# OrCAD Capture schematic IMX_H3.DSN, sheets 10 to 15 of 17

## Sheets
10 PAGE11 - ISM: size C
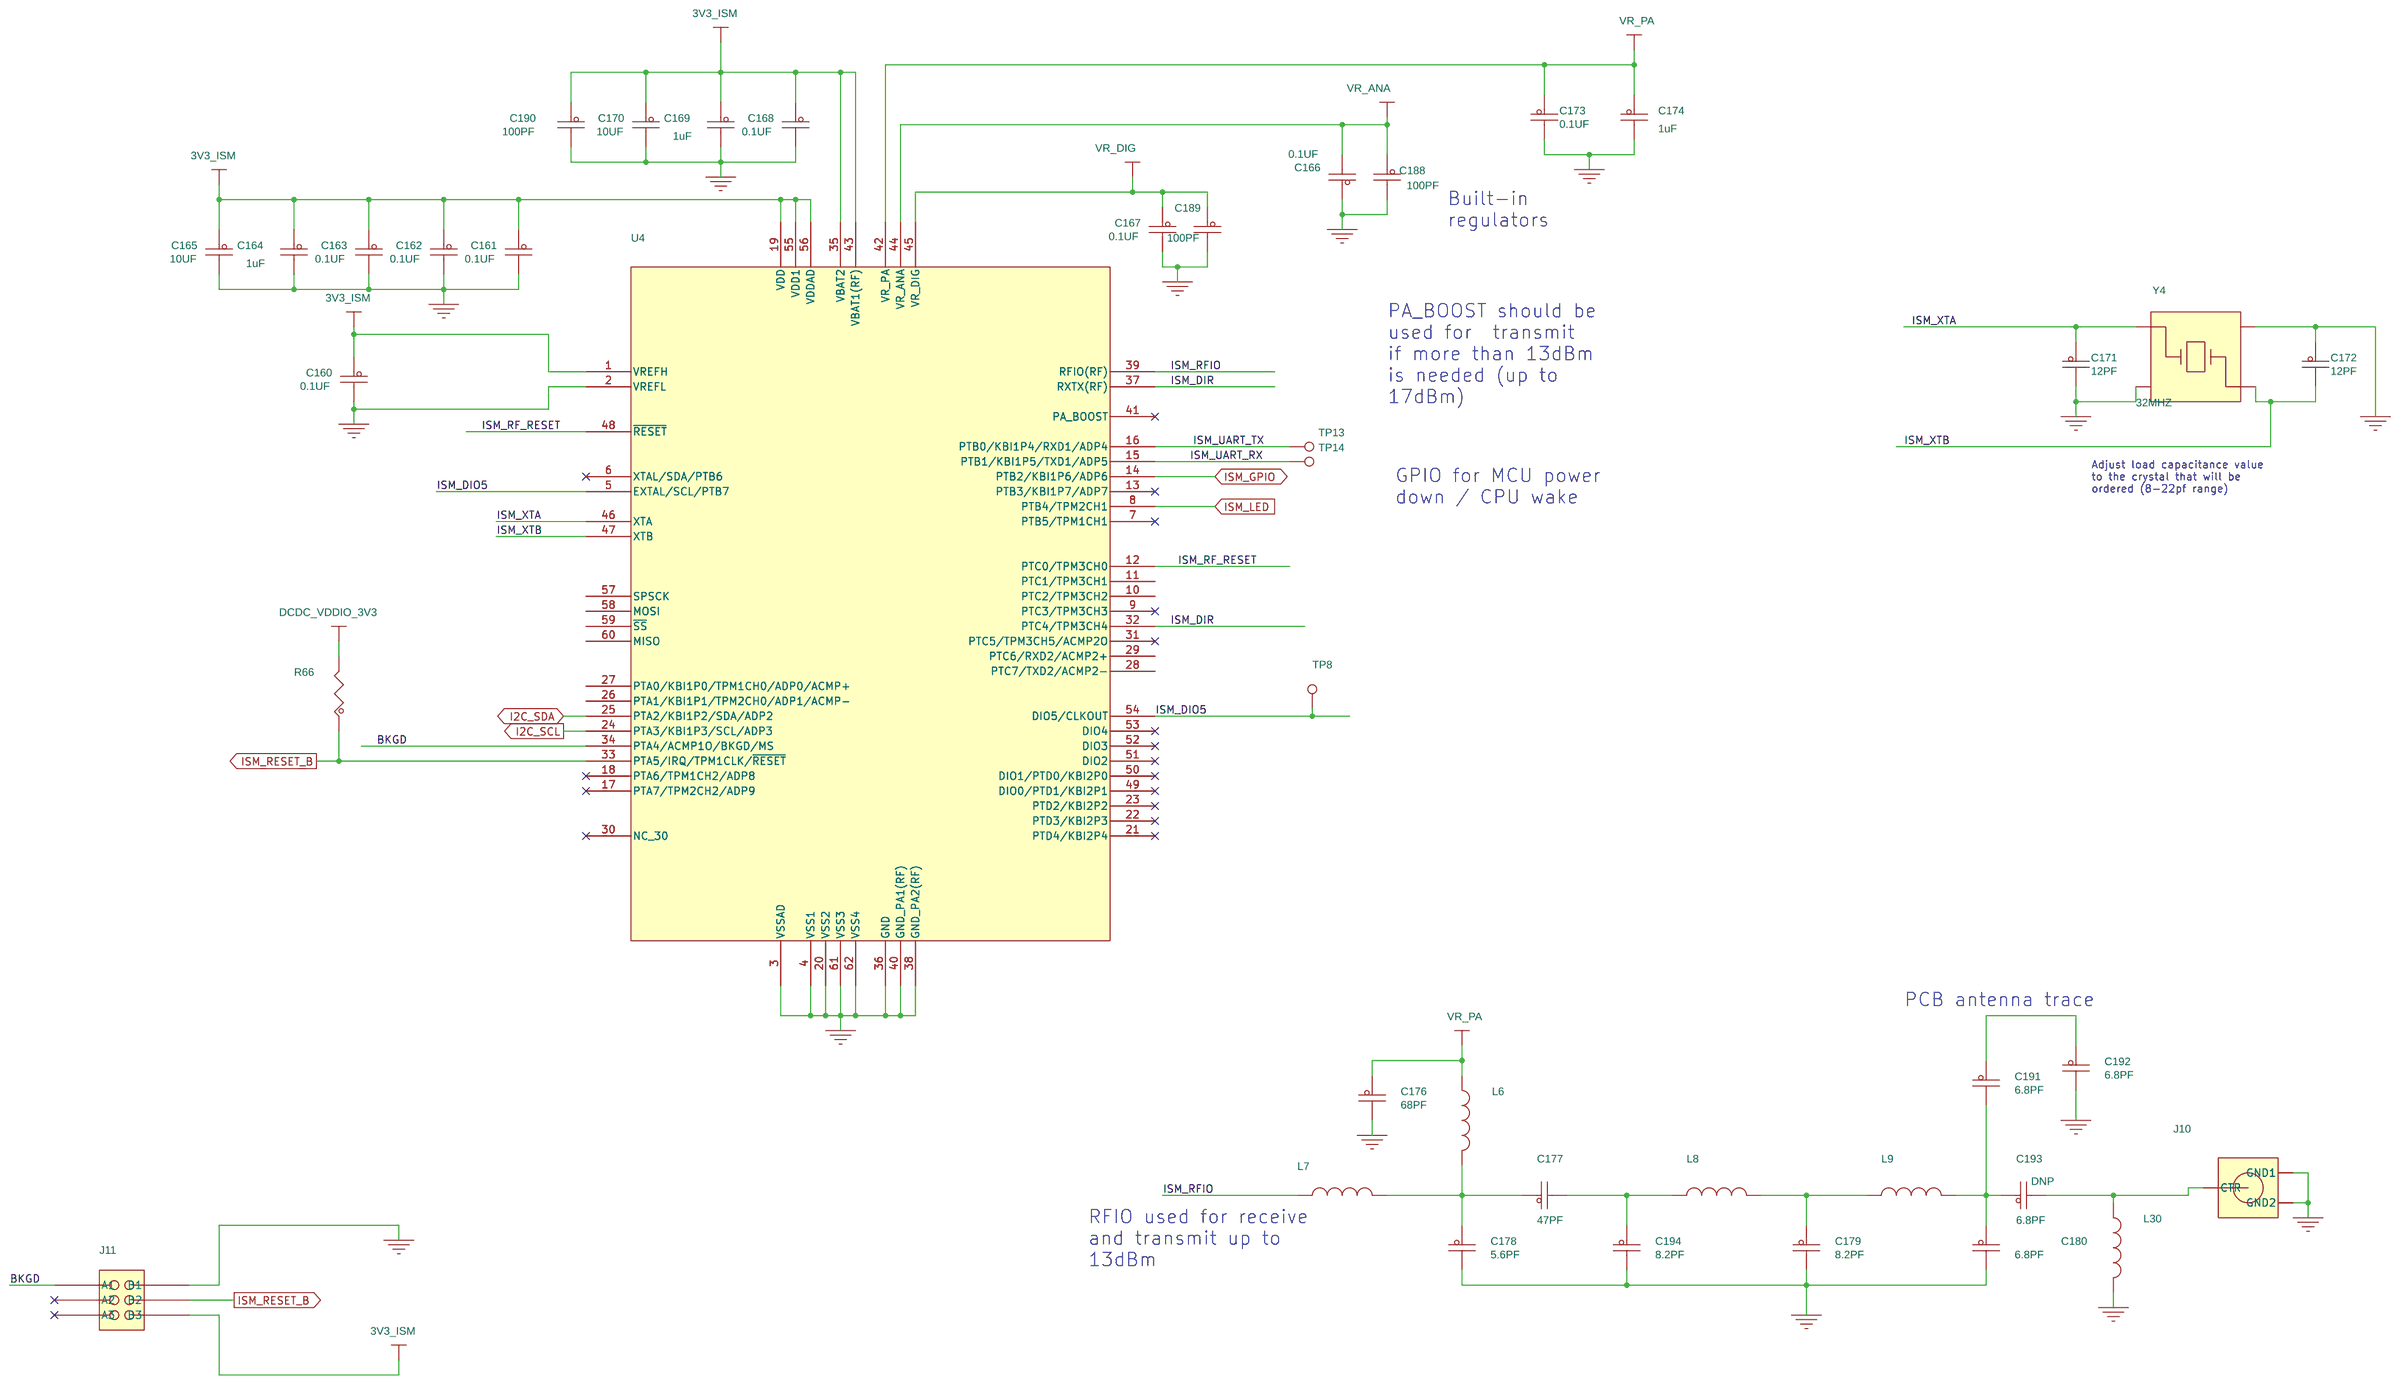
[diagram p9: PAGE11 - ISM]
11 PAGE12 - Zigbee: size C
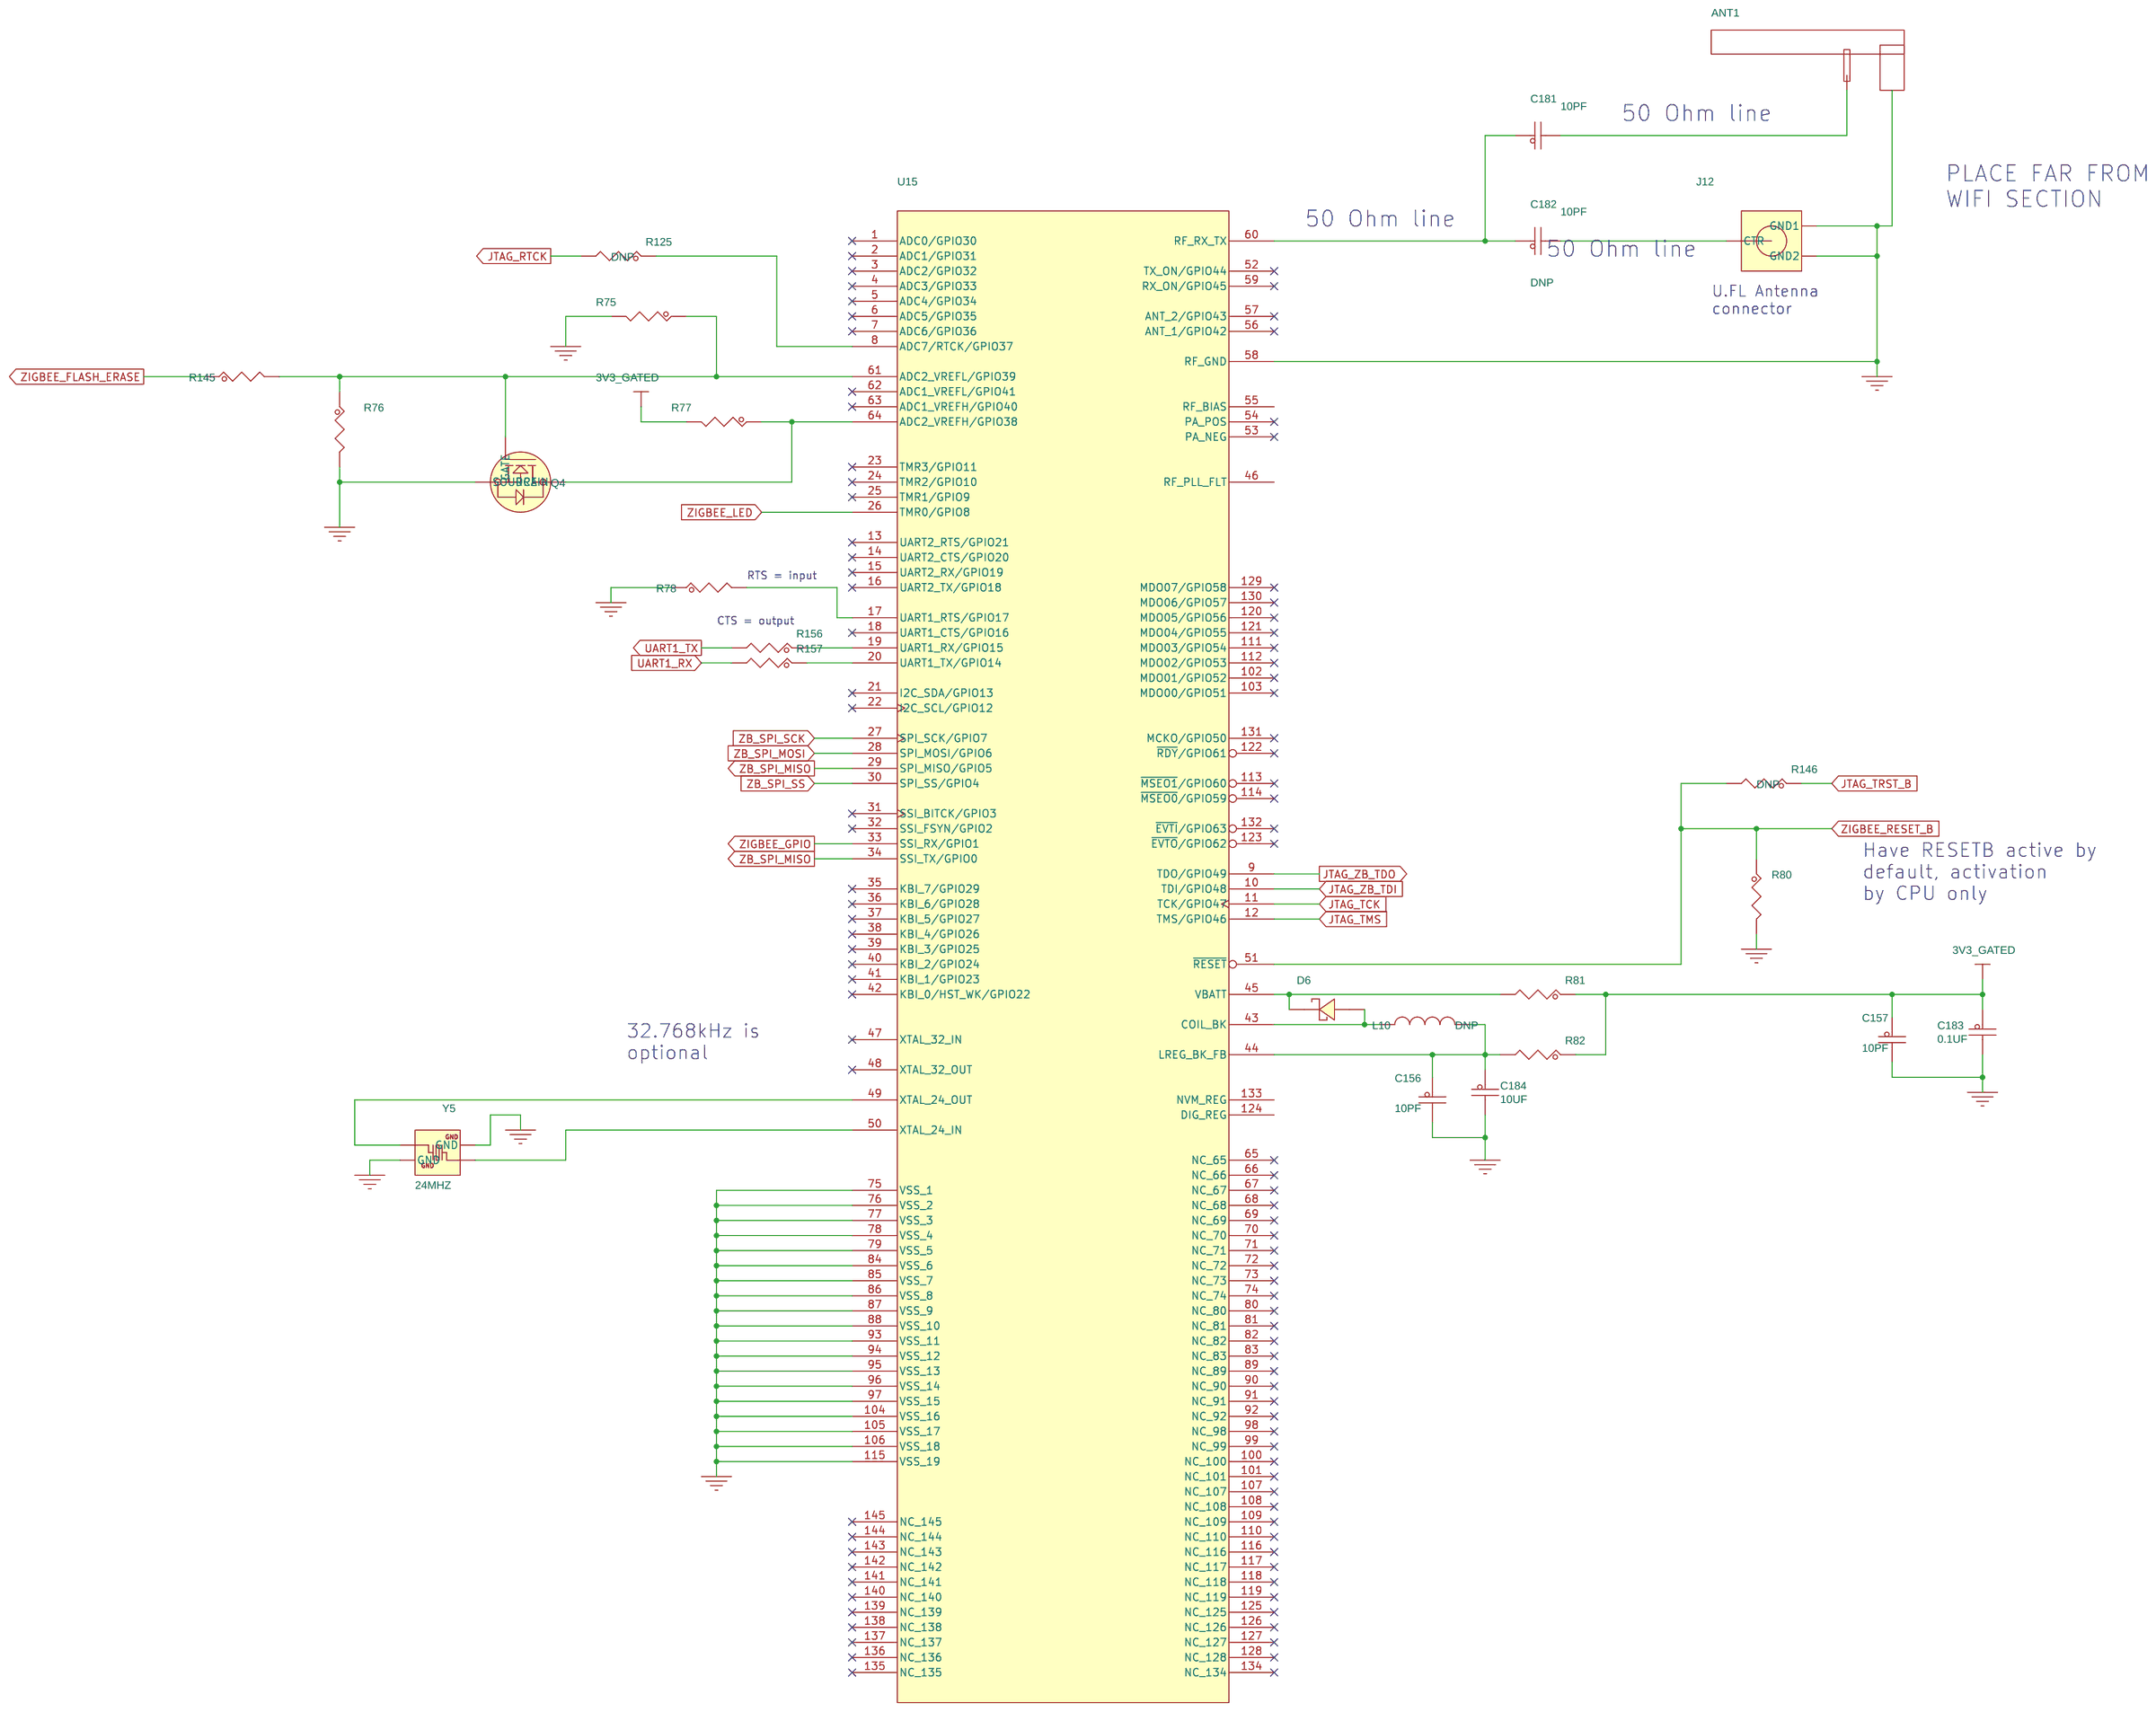
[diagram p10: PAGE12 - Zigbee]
12 PAGE13 - Audio: size C
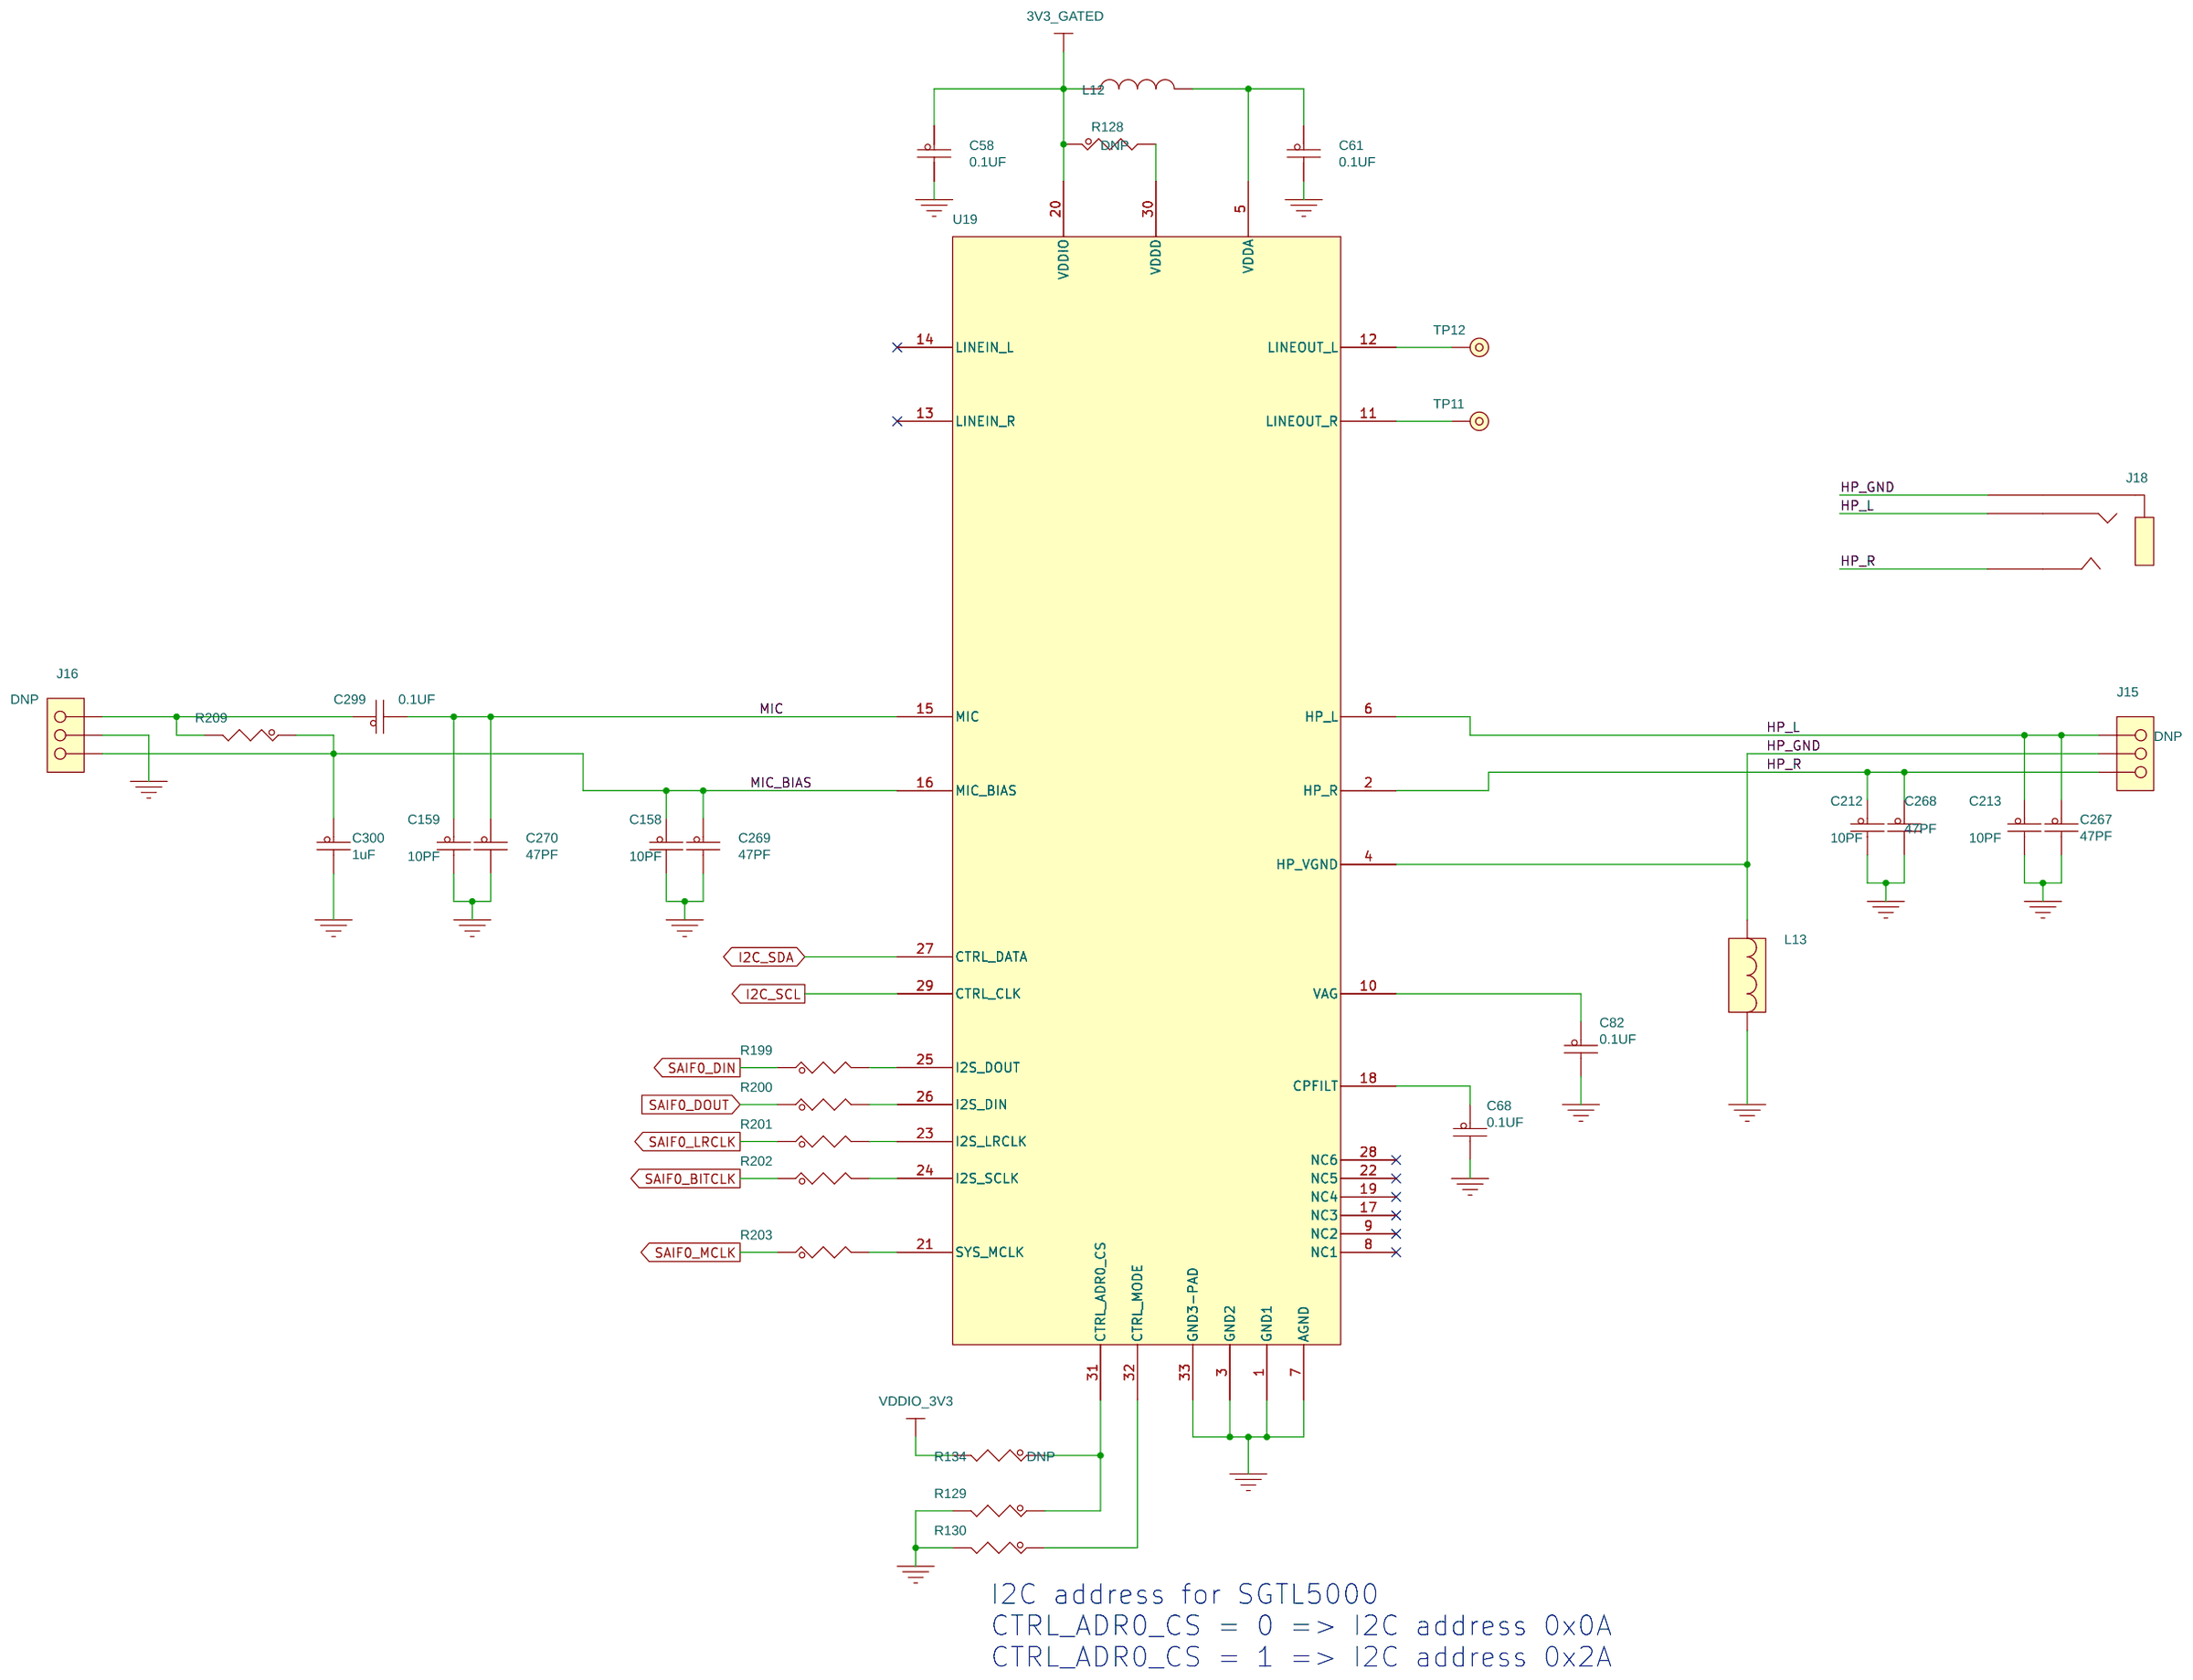
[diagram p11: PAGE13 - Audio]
13 PAGE14 - BlueTooth-WIFI: size C
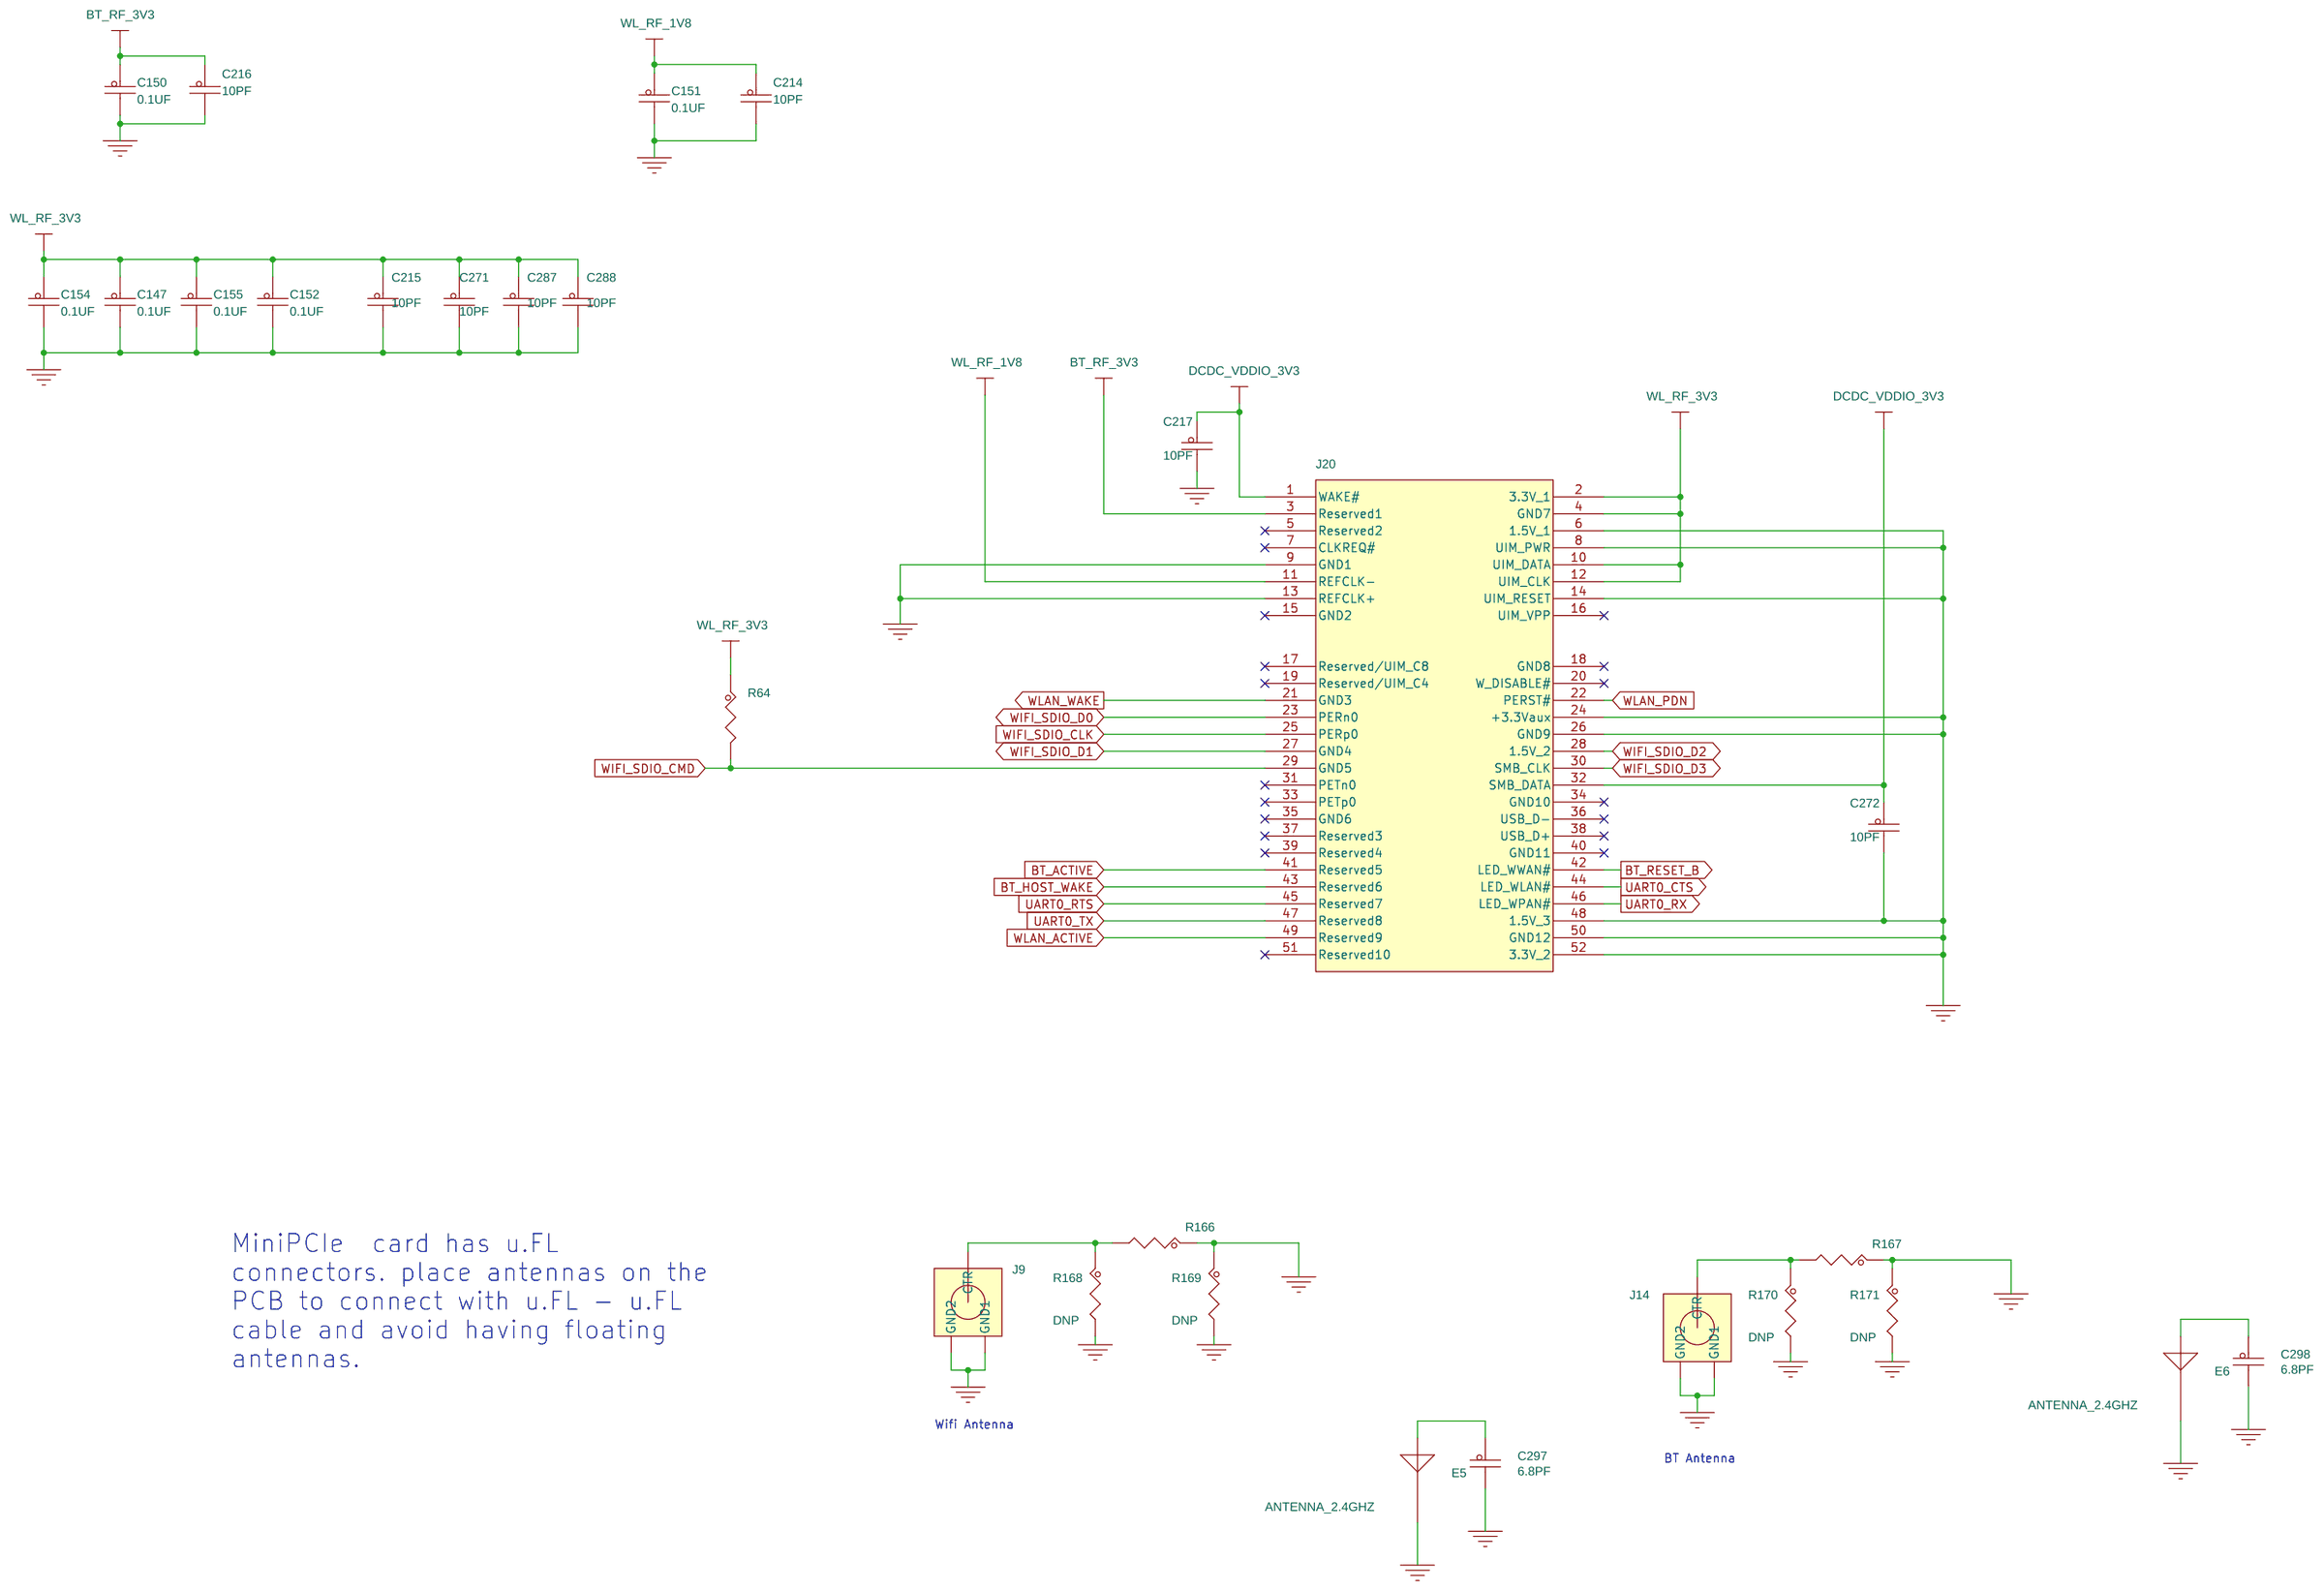
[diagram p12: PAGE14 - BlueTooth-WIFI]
14 PAGE15 - USB HUB: size C
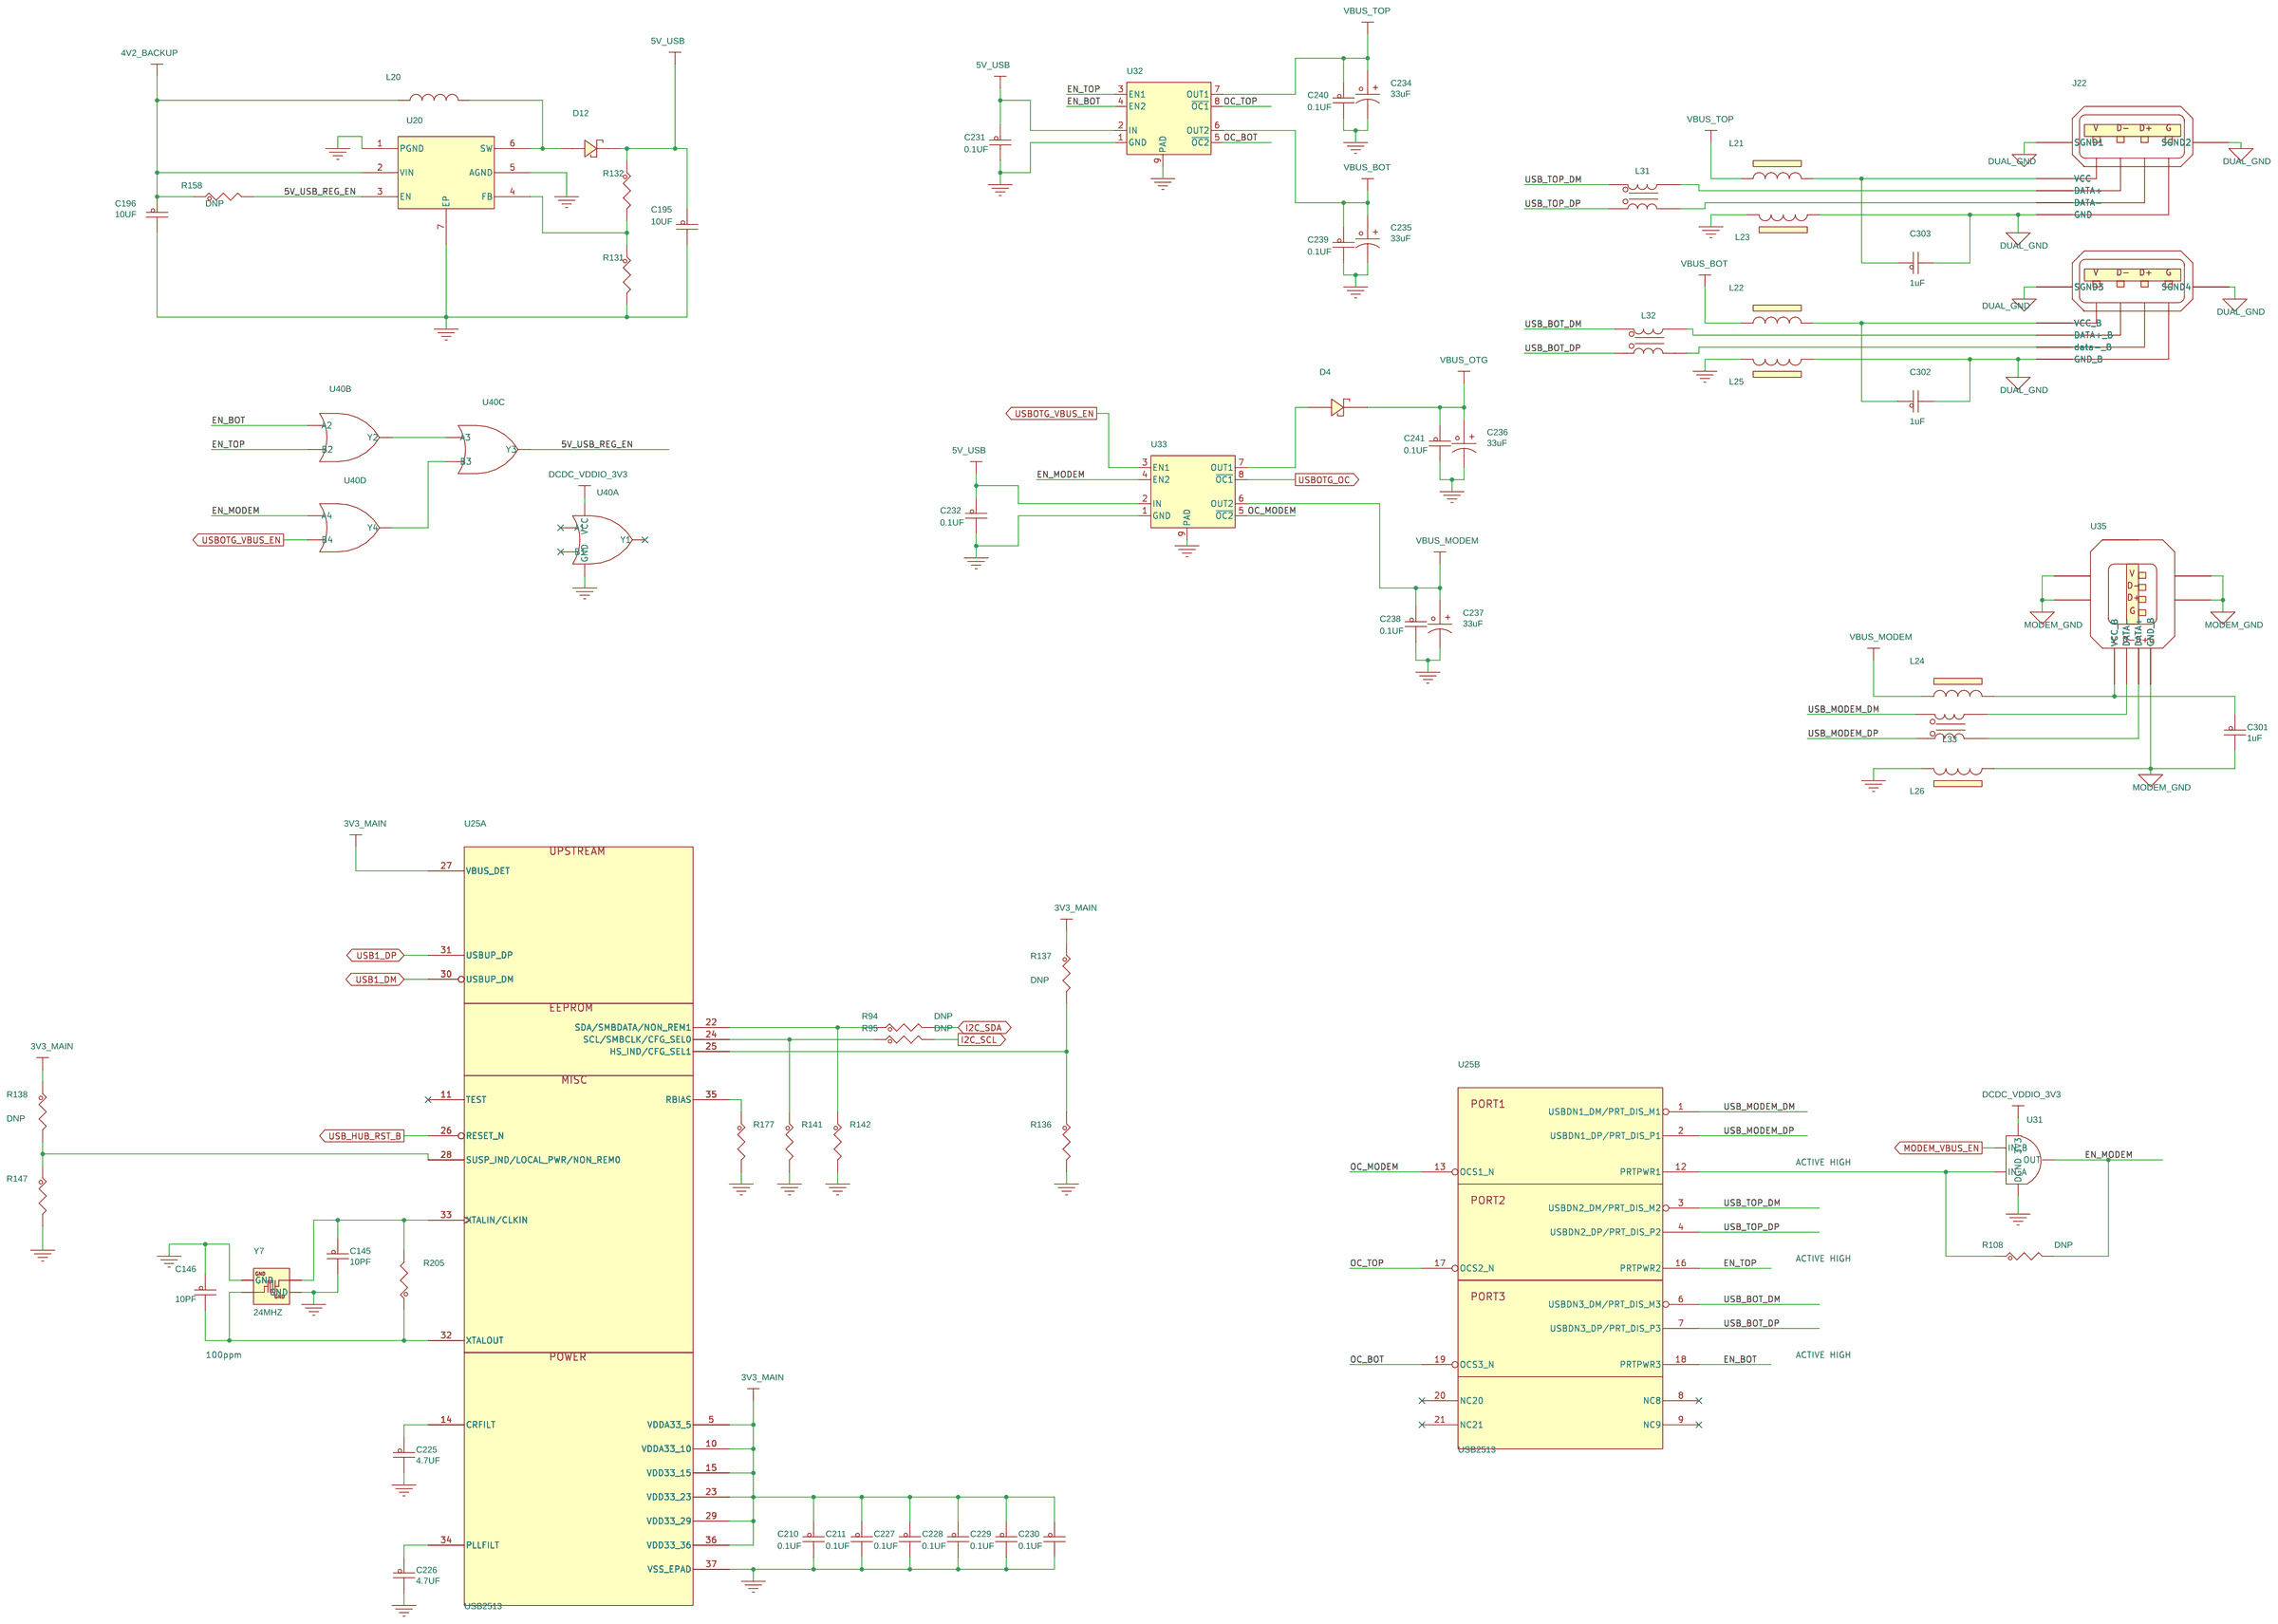
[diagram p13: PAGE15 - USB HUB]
15 PAGE16 - NFC , IO expander: size C
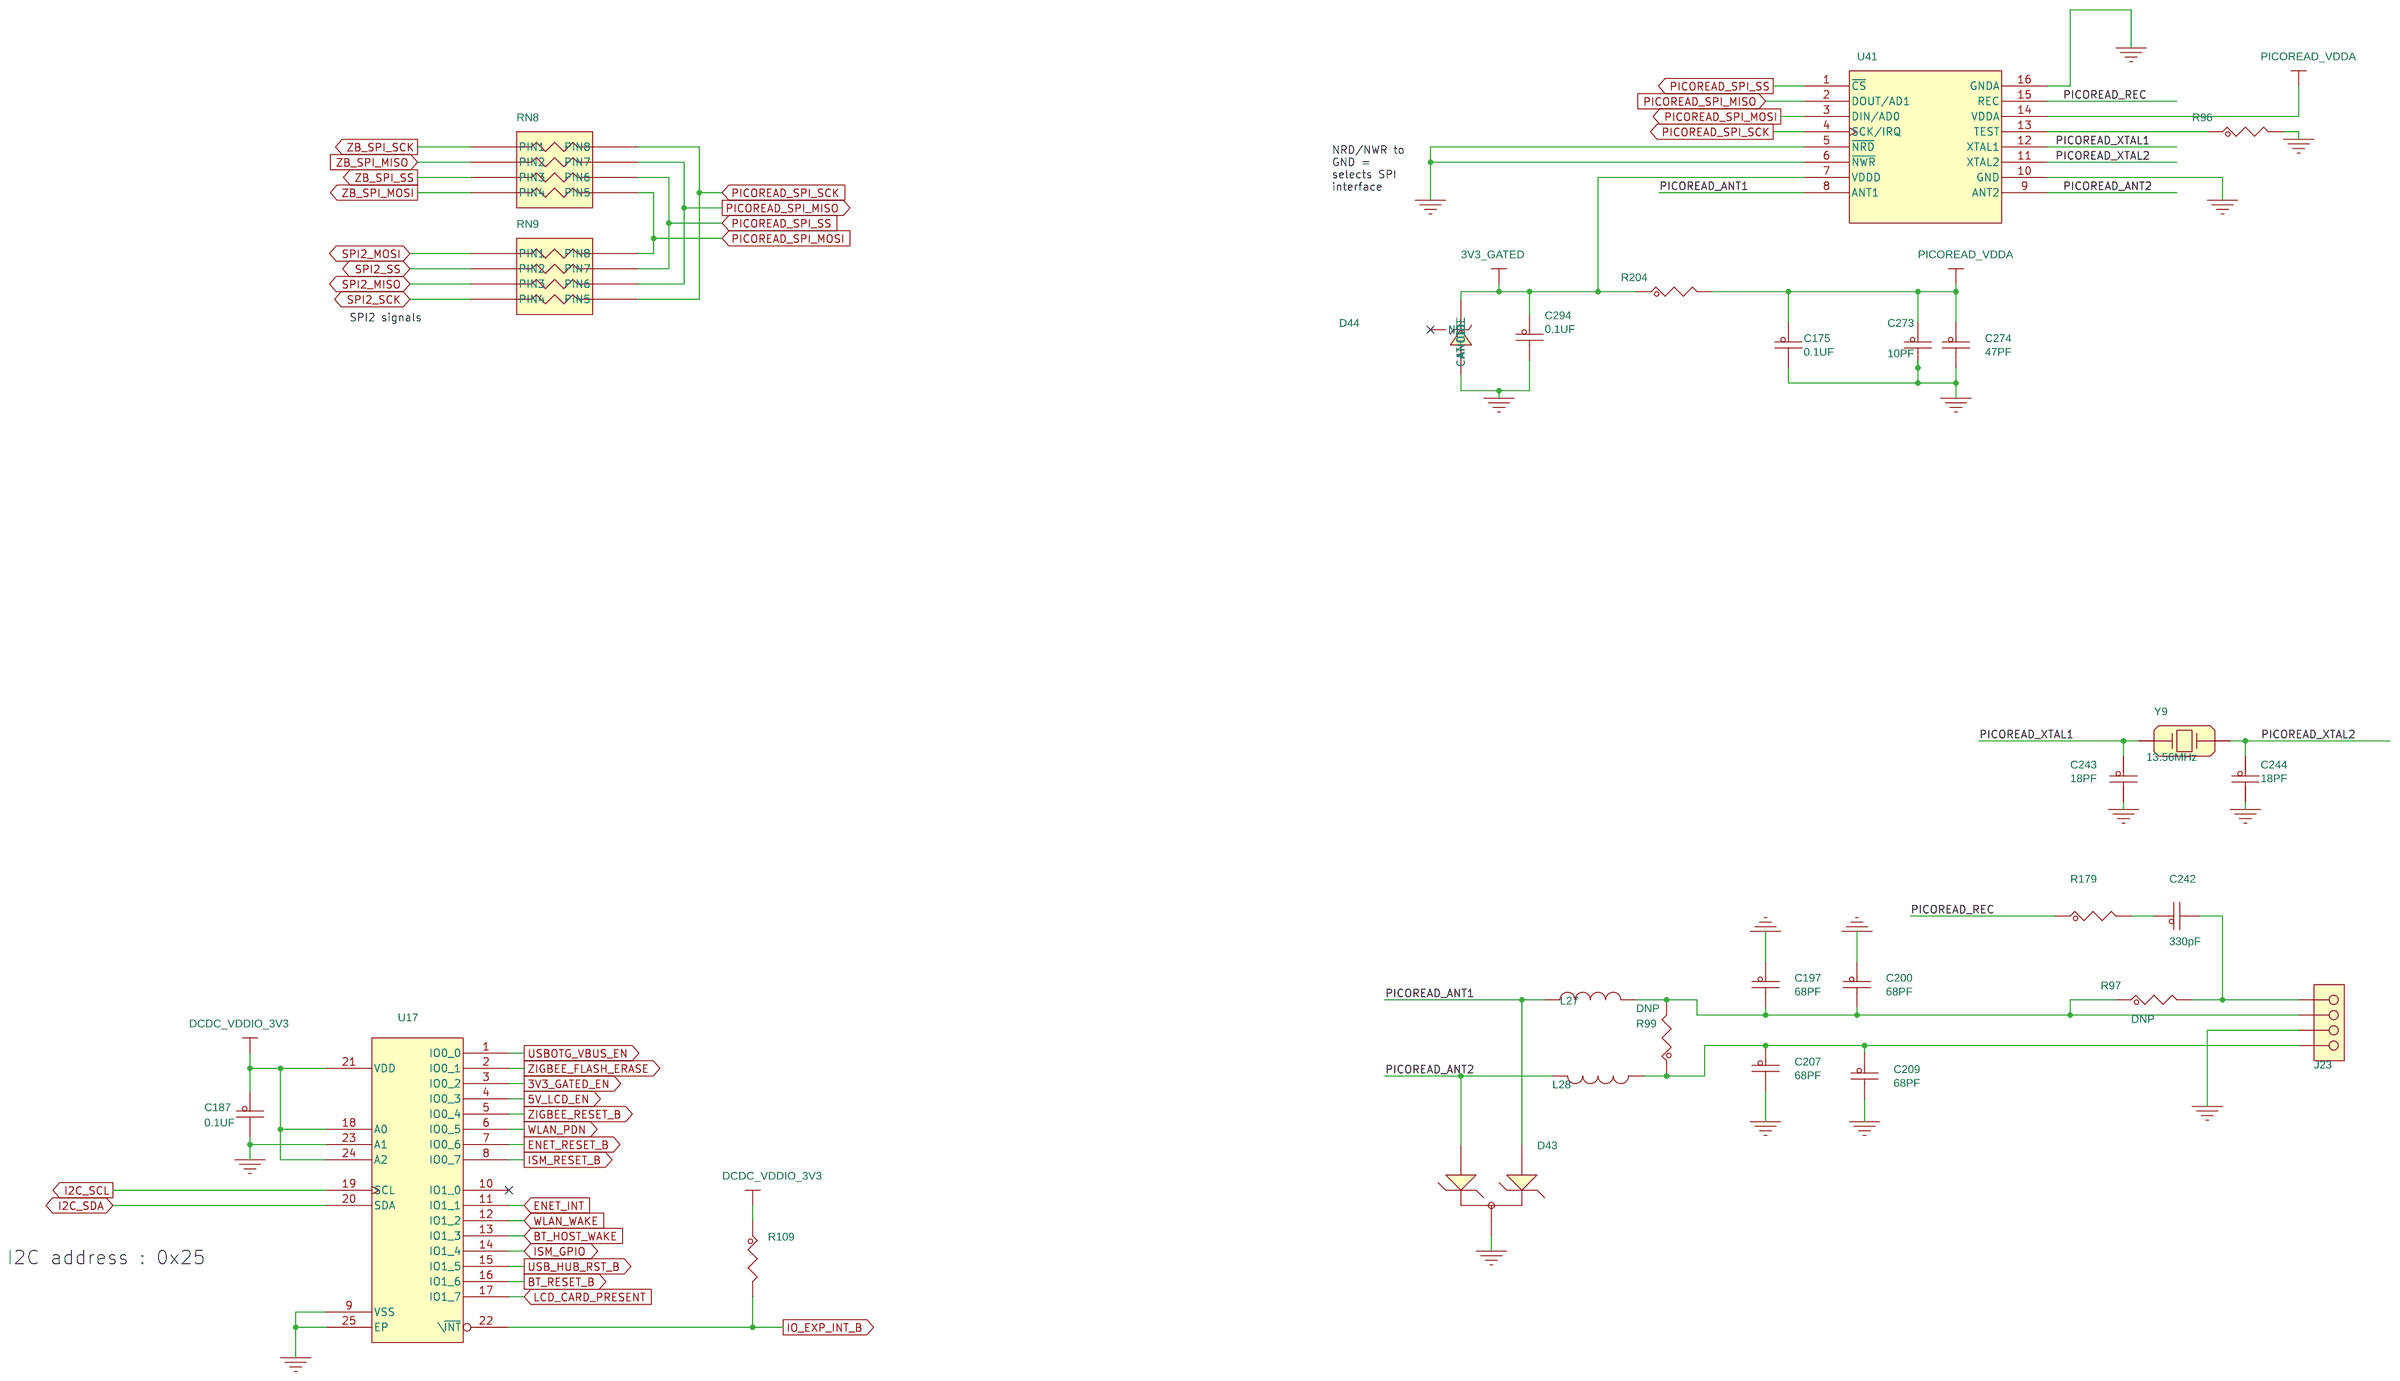
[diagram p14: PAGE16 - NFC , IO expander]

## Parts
sheet PAGE11 - ISM
C160  0.1UF  [CC0402_25]
C161  0.1UF  [CC0402_25]
C162  0.1UF  [CC0402_25]
C163  0.1UF  [CC0402_25]
C164  1uF  [CC0603_OV]
C165  10UF  [CC0805_OV]
C166  0.1UF  [CC0402_25]
C167  0.1UF  [CC0402_25]
C168  0.1UF  [CC0402_25]
C169  1uF  [CC0603_OV]
C170  10UF  [CC0805_OV]
C171  12PF  [CC0402_25]
C172  12PF  [CC0402_25]
C173  0.1UF  [CC0402_25]
C174  1uF  [CC0603_OV]
C176  68PF  [CC0402_25]
C177  47PF  [CC0402_25]
C178  5.6PF  [CC0402_25]
C179  8.2PF  [CC0402_25]
C180  6.8PF  [CC0402_25]
C188  100PF  [CC0402_25]
C189  100PF  [CC0402_25]
C190  100PF  [CC0402_25]
C191  6.8PF  [CC0402_25]
C192  6.8PF  [CC0402_25]
C193  6.8PF  [CC0402_25]
C194  8.2PF  [CC0402_25]
J10  U.FL  [CON_3_UFL_R_SMT]
J11  HDR_2X3  [HDR203_TSM2_SM]
L6  33nH  [IND_0402]
L7  4.7NH  [IND_0402]
L8  6.8NH  [IND_0402]
L9  6.8NH  [IND_0402]
L30  LQW18ANR27G00  [IND_0603A]
R66  10.0K  [RC0402_25]
TP8  35 MIL  [TESTPOINT_35MIL]
TP13  35 MIL  [TESTPOINT_35MIL]
TP14  35 MIL  [TESTPOINT_35MIL]
U4  MC12311  [lga60_0p5_8x8]
Y4  32MHZ  [xtlosc4_3p2x2p5mm_sm]
sheet PAGE12 - Zigbee
ANT1  F_Antenna  [f_antenna_dig528-2]
C156  10PF  [CC0402_25]
C157  10PF  [CC0402_25]
C181  10PF  [CC0402_25]
C182  10PF  [CC0402_25]
C183  0.1UF  [CC0402_25]
C184  10UF  [CC0805_OV]
D6  MBR0520LT1G  [SOD123]
J12  U.FL  [CON_3_UFL_R_SMT]
L10  100UH  [IND_VLF4018]
Q4  NTS4001NT1G  [sc70_3]
R75  10.0K  [RC0402_25]
R76  10.0K  [RC0402_25]
R77  10.0K  [RC0402_25]
R78  0  [RC0402_25]
R80  10.0K  [RC0402_25]
R81  0  [RC0402_25]
R82  0  [RC0402_25]
R125  0  [RC0402_25]
R145  0  [RC0402_25]
R146  0  [RC0402_25]
R156  0  [RC0402_25]
R157  0  [RC0402_25]
U15  MC13226V  [lga145_9p5_sq]
Y5  24MHZ  [xtlosc4_3p2x2p5mm_sm]
sheet PAGE13 - Audio
C58  0.1UF  [CC0402_25]
C61  0.1UF  [CC0402_25]
C68  0.1UF  [CC0402_25]
C82  0.1UF  [CC0402_25]
C158  10PF  [CC0402_25]
C159  10PF  [CC0402_25]
C212  10PF  [CC0402_25]
C213  10PF  [CC0402_25]
C267  47PF  [CC0402_25]
C268  47PF  [CC0402_25]
C269  47PF  [CC0402_25]
C270  47PF  [CC0402_25]
C299  0.1UF  [CC0402_25]
C300  1uF  [CC0603_OV]
J15  HDR_1X3  [hdr103_78mil]
J16  HDR_1X3  [hdr103_78mil]
J18  AUD 3  [con_aud_3_th_ra]
L12  470OHM  [IND_0603]
L13  75 OHM  [IND_0402]
R128  0  [RC0402_25]
R129  0  [RC0402_25]
R130  0  [RC0402_25]
R134  10.0K  [RC0402_25]
R199  10  [RC0402_25]
R200  10  [RC0402_25]
R201  10  [RC0402_25]
R202  10  [RC0402_25]
R203  10  [RC0402_25]
R209  0  [RC0402_25]
TP11  TEST_POINT  [testpoint_060_035mil]
TP12  TEST_POINT  [testpoint_060_035mil]
U19  SGTL5000 32QFN  [qfn32]
sheet PAGE14 - BlueTooth-WIFI
C147  0.1UF  [CC0402_25]
C150  0.1UF  [CC0402_25]
C151  0.1UF  [CC0402_25]
C152  0.1UF  [CC0402_25]
C154  0.1UF  [CC0402_25]
C155  0.1UF  [CC0402_25]
C214  10PF  [CC0402_25]
C215  10PF  [CC0402_25]
C216  10PF  [CC0402_25]
C217  10PF  [CC0402_25]
C271  10PF  [CC0402_25]
C272  10PF  [CC0402_25]
C287  10PF  [CC0402_25]
C288  10PF  [CC0402_25]
C297  6.8PF  [CC0402_25]
C298  6.8PF  [CC0402_25]
E5  ANTENNA_2.4GHZ  [antenna_3316]
E6  ANTENNA_2.4GHZ  [antenna_3316]
J9  U.FL  [CON_3_UFL_R_SMT]
J14  U.FL  [CON_3_UFL_R_SMT]
J20  CON 2X26 MINI PCI EXPRESS  [con_2x26_0p8_smt_a]
R64  22K  [RC0402_25]
R166  0  [RC0402_25]
R167  0  [RC0402_25]
R168  0  [RC0402_25]
R169  0  [RC0402_25]
R170  0  [RC0402_25]
R171  0  [RC0402_25]
sheet PAGE15 - USB HUB
C145  10PF  [CC0402_25]
C146  10PF  [CC0402_25]
C195  10UF  [CC0805_OV]
C196  10UF  [CC0805_OV]
C210  0.1UF  [CC0402_25]
C211  0.1UF  [CC0402_25]
C225  4.7UF  [CC0603_OV]
C226  4.7UF  [CC0603_OV]
C227  0.1UF  [CC0402_25]
C228  0.1UF  [CC0402_25]
C229  0.1UF  [CC0402_25]
C230  0.1UF  [CC0402_25]
C231  0.1UF  [CC0402_25]
C232  0.1UF  [CC0402_25]
C234  33uF  [cc3216]
C235  33uF  [cc3216]
C236  33uF  [cc3216]
C237  33uF  [cc3216]
C238  0.1UF  [CC0402_25]
C239  0.1UF  [CC0402_25]
C240  0.1UF  [CC0402_25]
C241  0.1UF  [CC0402_25]
C301  1uF  [CC0603_OV]
C302  1uF  [CC0603_OV]
C303  1uF  [CC0603_OV]
D4  MBR120LSFT1G  [SOD123]
D12  MBR120LSFT1G  [SOD123]
J22  USB_TYPE_A_DUAL  [AMP-787745-X]
L20  10uH  [ind_ihlp_2020]
L21  470 Ohm  [IND_0603]
L22  470 Ohm  [IND_0603]
L23  470 Ohm  [IND_0603]
L24  470 Ohm  [IND_0603]
L25  470 Ohm  [IND_0603]
L26  470 Ohm  [IND_0603]
L31  90 OHM@100MHZ  [IND_0805_4P]
L32  90 OHM@100MHZ  [IND_0805_4P]
L33  90 OHM@100MHZ  [IND_0805_4P]
R94  0  [RC0402_25]
R95  0  [RC0402_25]
R108  0  [RC0402_25]
R131  10.0K  [RC0402_25]
R132  30.1K  [RC0402_25]
R136  10.0K  [RC0402_25]
R137  10.0K  [RC0402_25]
R138  10.0K  [RC0402_25]
R141  10.0K  [RC0402_25]
R142  10.0K  [RC0402_25]
R147  10.0K  [RC0402_25]
R158  10.0K  [RC0402_25]
R177  12.0K  [RC0402_25]
R205  1.0M  [RC0402_25]
U20  LM2735X  [llp6_0p95_3x3]
U25  USB2513  [QFN36]  (sections A,B)
U31  NC7SZ08P5  [SC70-5]
U32  TPS2064  [MSOP8_0p65_3p1x3p1]
U33  TPS2064  [MSOP8_0p65_3p1x3p1]
U35  USB_TYPE_A  [CON_4_USB]
U40  MC74HC32A  [tssop14_a]  (sections A,B,C,D)
Y7  24MHZ  [xtlosc4_3p2x2p5mm_sm]
sheet PAGE16 - NFC , IO expander
C175  0.1UF  [CC0402_25]
C187  0.1UF  [CC0402_25]
C197  68PF  [CC0402_25]
C200  68PF  [CC0402_25]
C207  68PF  [CC0402_25]
C209  68PF  [CC0402_25]
C242  330pF  [CC0402_25]
C243  18PF  [CC0402_25]
C244  18PF  [CC0402_25]
C273  10PF  [CC0402_25]
C274  47PF  [CC0402_25]
C294  0.1UF  [CC0402_25]
D43  BAT54C  [sot-23]
D44  BZX84C11LT1G  [SOT23]
J23  HDR 1X4  [hdr104_929]
L27  2.2uH  [IND_0402]
L28  2.2uH  [IND_0402]
R96  0  [RC0402_25]
R97  0  [RC0402_25]
R99  0  [RC0402_25]
R109  10.0K  [RC0402_25]
R179  220K  [RC0402_25]
R204  0  [RC0805_OV]
RN8  0  [CRN_8_0P5_2X1]
RN9  0  [CRN_8_0P5_2X1]
U17  PCA9555BS  [qfn24_4X4_ep2p25mm]
U41  PICOREAD  [SSOP16]
Y9  13.56MHz  [XTAL_CS10_SM]

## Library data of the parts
C58 C61 C68 C82 C147 C150-C152 C154 C155 C160-C163 C166-C168 C173 C175 C183 C187 C210 C211 C227-C232 C238-C241 C294 C299 = CAP_NP: CAP CER 0.1UF 10V 10% X5R 0402; AGILE_PN: 150-75634; CAD_APPROVED: Yes; FPLIST: CC0402_25,CC0402_HD,0402_CC; HEIGHT: 0.60MM; MFG_NAME01: KEMET; MFG_PN01: C0402C104K8PAC; ROHS: Yes; Tolerance: 10%
C164 C169 C174 C300-C303 = CAP_NP: CAP CER 1UF 16V 10% X7R 0603; CAD_APPROVED: Yes; FPLIST: CC0603_OV,CC0603,0603_CC; HEIGHT: 0.84mm; MFG_NAME01: TAIYO YUDEN; MFG_PN01: EMK107B7105KA-T; ROHS: Yes; Tolerance: 10%
C165 C170 C184 C195 C196 = CAP_NP: CAP CER 10UF 10V 10% X5R 0805; CAD_APPROVED: Yes; FPLIST: CC0805_OV,CC0805,0805_CC; HEIGHT: 1.45 MM; MFG_NAME01: SAMSUNG; MFG_PN01: CL21A106KPFNNNE; ROHS: Yes; Tolerance: 10%
C171 C172 = CAP_NP: CAP CER 12PF 50V 5% C0G 0402; CAD_APPROVED: Yes; FPLIST: CC0402_25,CC0402_HD,0402_CC; HEIGHT: 0.55MM; MFG_NAME01: MURATA; MFG_PN01: GRM1555C1H120JZ01D; ROHS: Yes; Tolerance: 25%
C176 C197 C200 C207 C209 = CAP_NP: CAP CER 68PF 25V 5% COG 0402; CAD_APPROVED: Yes; FPLIST: CC0402_25,CC0402_HD,0402_CC; HEIGHT: 0.55MM; MFG_NAME01: AVX; MFG_PN01: 04023A680JAT2A; ROHS: Yes; Tolerance: 5%
C177 = CAP_NP: CAP CER 47PF 50V 5% C0G 0402; CAD_APPROVED: Yes; FPLIST: CC0402_25,CC0402_HD,0402_CC; HEIGHT: 0.64 MM; MFG_NAME01: AVX; MFG_PN01: 04025A470JAT2A; ROHS: Yes; Tolerance: 5%
C178 = CAP_NP: CAP CER 5.6PF 50V +/-0.25PF C0G CC0402; AGILE_PN: 150-75521; CAD_APPROVED: Yes; FPLIST: CC0402_25,CC0402_HD,0402_CC; HEIGHT: 0.55MM; MFG_NAME01: MURATA; MFG_PN01: GJM1555C1H5R6CB01D; ROHS: Yes; Tolerance: 0.25PF
C179 C194 = CAP_NP: CAP CER 8.2PF 25V 0.25PF C0G 0402; AGILE_PN: 150-30084; CAD_APPROVED: Yes; FPLIST: CC0402_25,CC0402_HD,0402_CC; HEIGHT: 0.56MM; MFG_NAME01: AVX; MFG_PN01: 04023U8R2CAT2A; ROHS: Yes; Tolerance: 0.25PF
C180 C191 C192 C297 C298 = CAP_NP: CAP CER 6.8PF 50V 0.5PF C0G 0402; CAD_APPROVED: Yes; FPLIST: CC0402_25,CC0402_HD,0402_CC; HEIGHT: 0.55MM; MFG_NAME01: MURATA; MFG_PN01: GRM1555C1H6R8DZ01D; ROHS: Yes; Tolerance: 0.5PF %
C188-C190 = CAP_NP: CAP CER 100PF 50V 5% X7R 0402; CAD_APPROVED: Yes; FPLIST: CC0402_25,CC0402_HD,0402_CC; HEIGHT: 0.55MM; MFG_NAME01: AVX; MFG_PN01: 04025A101JAT2A; ROHS: Yes; Tolerance: 10%
C193 = CAP_NP: CAP CER 6.8PF 50V 0.5PF C0G 0402; ASSY_OPT: DNP; CAD_APPROVED: Yes; FPLIST: CC0402_25,CC0402_HD,0402_CC; HEIGHT: 0.55MM; MFG_NAME01: MURATA; MFG_PN01: GRM1555C1H6R8DZ01D; ROHS: Yes; Tolerance: 0.5PF %
J9 J10 J12 J14 = UFL: CON 1 COAX SKT SMT -- AU; AGILE_PN: 211-30001; CAD_APPROVED: Yes; HEIGHT: 1.25 MM; MFG_NAME01: HIROSE; MFG_PN01: U.FL-R-SMT(01); ROHS: Yes
J11 = CONN_HDR_3X2: HDR 2X3 SMT 100MIL CTR 390H AU; AGILE_PN: 211-75231; CAD_APPROVED: Yes; HEIGHT: 9.91 MM; MFG_NAME01: SAMTEC; MFG_PN01: TSM-103-01-SM-DV-P-TR; ROHS: Yes
L6 = INDUCTOR: IND -- 0.033UH@100MHZ 200MA 5% 0402; AGILE_PN: 180-75099; CAD_APPROVED: YES; FPLIST: IND_0402,0402_CC; HEIGHT: 0.55MM; MFG_NAME01: TOKO INC.; MFG_PN01: LL1005-FHL33NJ; ROHS: Yes; Tolerance: 5%
L7 = INDUCTOR: IND -- 4.7NH@100MHZ 300MA 0.3NH 0402; AGILE_PN: 180-76555; CAD_APPROVED: Yes; FPLIST: IND_0402,0402_CC; HEIGHT: 0.55MM; MFG_NAME01: TAIYO YUDEN; MFG_PN01: HK10054N7S-T; ROHS: Yes; Tolerance: 0.3NH
L8 L9 = INDUCTOR: IND -- 6.8NH@100MHZ 300MA 5% 0402; AGILE_PN: 180-76556; CAD_APPROVED: Yes; FPLIST: IND_0402,0402_CC; HEIGHT: 0.55MM; MFG_NAME01: TAIYO YUDEN; MFG_PN01: HK10056N8J-T; ROHS: Yes; Tolerance: 5%
L30 = INDUCTOR: IND CHK 270NH@100MHZ 220MA 5% 0603; AGILE_PN: 180-77677; CAD_APPROVED: Yes; FPLIST: IND_0603A,0603_CC; HEIGHT: 1 MM; MFG_NAME01: MURATA; ROHS: Yes; Tolerance: 5%
R66 R75-R77 R80 R109 R131 R136 R141 R142 R147 = RES: RES MF 10.0K 1/16W 1% 0402; AGILE_PN: 470-75416; CAD_APPROVED: Yes; FPLIST: RC0402_25,RC0402_HD,0402_CC; MFG_NAME01: KOA SPEER; MFG_PN01: RK73H1ETTP1002F; ROHS: Yes; Tolerance: 1%
TP8 TP13 TP14 = Test_pad: TEST PAD 35 MIL ROUND SMT; NO PART TO ORDER; AGILE_PN: 510-75219; CAD_APPROVED: Yes; HEIGHT: 0.1 MM; ROHS: Yes
U4 = MC12311_LGA_60P: IC MCU 8BIT 32KB FLASH 2KB RAM 50MHZ 1.8-3.6V LGA60; AGILE_PN: TMP-WF-14692; CAD_APPROVED: Yes; HEIGHT: 0.98MM; MFG_NAME01: Freescale Semiconductor; PRE_APN: 344-01203; ROHS: Yes
Y4 = XTAL_13Y: XTAL 32MHZ 9PF -- SMT 3.2X2.5MM; CAD_APPROVED: Yes; HEIGHT: 0.6MM; MFG_NAME01: NDK; MFG_PN01: NX3225SA-32.000000MHZ; ROHS: Yes
ANT1 = F_Antenna: PCB F ANTENNA, NO PART ORDER; AGILE_PN: 510-75678; CAD_APPROVED: Yes; HEIGHT: 0MM; MFG_NAME01: NOT A PART; MFG_PN01: NOT A PART; ROHS: Yes
C145 C146 C156-C159 C181 C212 C213 = CAP_NP: CAP CER 10PF 16V 0.25PF C0G 0402; CAD_APPROVED: Yes; FPLIST: CC0402_25,CC0402_HD,0402_CC; HEIGHT: 0.55MM; MFG_NAME01: MURATA; MFG_PN01: GRM1555C1H100JZ01D; ROHS: Yes; Tolerance: 0.25PF
C182 = CAP_NP: CAP CER 10PF 16V 0.25PF C0G 0402; ASSY_OPT: DNP; CAD_APPROVED: Yes; FPLIST: CC0402_25,CC0402_HD,0402_CC; HEIGHT: 0.55MM; MFG_NAME01: MURATA; MFG_PN01: GRM1555C1H100JZ01D; ROHS: Yes; Tolerance: 0.25PF
D6 = DIODE_SCHTKY: DIODE SCH 0.5A 20V SOD-123; AGILE_PN: 480-75176; CAD_APPROVED: Yes; HEIGHT: 1.45MM; MFG_NAME01: ON SEMICONDUCTOR; ROHS: Yes
L10 = IND: IND PWR 100UH@100KHZ 0.33A 20% SMT; AGILE_PN: 180-77056; ASSY_OPT: DNP; CAD_APPROVED: Yes; HEIGHT: 2.8MM; MFG_NAME01: TDK; MFG_PN01: VLCF4028T-101MR33-2; PART_TYPE: INDUCTOR\POWER; ROHS: Yes; Tolerance: 20%
Q4 = MOSFET_N: TRAN NMOS SW 30V 270MA SC-70; AGILE_PN: 480-76278; CAD_APPROVED: Yes; HEIGHT: 1.0MM; MFG_NAME01: ON SEMICONDUCTOR; ROHS: Yes
R78 R81 R82 R96 R145 R156 R157 R166 R167 = RES: RES MF ZERO OHM 1/16W 5% 0402; AGILE_PN: 470-75394; CAD_APPROVED: Yes; FPLIST: RC0402_25,RC0402_HD,RC0402_X2,0402_CC; MFG_NAME01: ROHM; MFG_PN01: MCR01MZPJ000; ROHS: Yes; Tolerance: 5%
R94 R95 R97 R99 R108 R125 R128 R146 R168-R171 = RES: RES MF ZERO OHM 1/16W 5% 0402; AGILE_PN: 470-75394; ASSY_OPT: DNP; CAD_APPROVED: Yes; FPLIST: RC0402_25,RC0402_HD,RC0402_X2,0402_CC; MFG_NAME01: ROHM; MFG_PN01: MCR01MZPJ000; ROHS: Yes; Tolerance: 5%
U15 = MC13224V_145P: IC MCU ARM7 32BIT 26MHZ 2.0-3.6V LGA99; AGILE_PN: 312-79715; CAD_APPROVED: Yes; HEIGHT: 1.2 MM; MFG_NAME01: FREESCALE SEMICONDUCTOR; ROHS: Yes
Y5 Y7 = CRYSTAL_JXS63: XTAL 24MHZ -- 30PPM 3.2X2.5MM SMD; CAD_APPROVED: Yes; HEIGHT: 0.9MM; MFG_NAME01: TXC CORP; MFG_PN01: 7V-24.000MAAE-T; ROHS: Yes
C267-C270 C274 = CAP_NP: CAP CER 47PF 50V 5% C0G 0402; CAD_APPROVED: YES; FPLIST: CC0402_25,CC0402_HD,0402_CC; HEIGHT: 0.56MM; MFG_NAME01: AVX; MFG_PN01: 04025A470JAT2A; ROHS: Yes; Tolerance: 5%
J15 J16 = CONN_HDR_3X1: HDR 1X3 TH 2MM SP 217H AU 110L; AGILE_PN: 210-77092; ASSY_OPT: DNP; CAD_APPROVED: Yes; HEIGHT: 5.2MM; MFG_NAME01: SAMTEC; MFG_PN01: TMM-103-02-G-S; ROHS: Yes
J18 = 3.5MM_STEREO_JACK: CON 3 AUD JACK 3.5MM SKT RA TH -- 484H SN 130L; AGILE_PN: 210-78359; CAD_APPROVED: Yes; HEIGHT: 12.3mm; MFG_NAME01: CUI STACK; MFG_PN01: SJ1-3533NG; ROHS: Yes
L12 = INDUCTOR: IND FER BEAD 470OHM@100MHZ 500MA 25% 0603; AGILE_PN: 180-76158; CAD_APPROVED: Yes; FPLIST: IND_0603,0603_CC; HEIGHT: 0.95MM; MFG_NAME01: MURATA; MFG_PN01: BLM18EG471SN1D; ROHS: Yes; Tolerance: 25%
L13 = BEAD: IND FER BEAD 600 OHM@100MHZ 300MA 25% 0402; AGILE_PN: 180-77595; CAD_APPROVED: Yes; FPLIST: IND_0402,0402_CC; HEIGHT: 0.55MM; MFG_NAME01: MuRata; MFG_PN01: BLM15HD601SN1D; PART_TYPE: FERRITE\BEAD; ROHS: Yes; Tolerance: 25%
R129 R130 R209 = RES: RES MF ZERO OHM 1/16W 5% 0402; AGILE_PN: 470-75394; CAD_APPROVED: Yes; FPLIST: RC0402_25,RC0402_HD,0402_CC; MFG_NAME01: ROHM; MFG_PN01: MCR01MZPJ000; ROHS: Yes; Tolerance: 5%
R134 R137 R138 R158 = RES: RES MF 10.0K 1/16W 1% 0402; AGILE_PN: 470-75416; ASSY_OPT: DNP; CAD_APPROVED: Yes; FPLIST: RC0402_25,RC0402_HD,0402_CC; MFG_NAME01: KOA SPEER; MFG_PN01: RK73H1ETTP1002F; ROHS: Yes; Tolerance: 1%
R199-R203 = RES: RES MF 10 OHM 1/16W 5% 0402; CAD_APPROVED: Yes; FPLIST: RC0402_25,RC0402_HD,0402_CC; MFG_NAME01: Stackpole Electronics; MFG_PN01: RMCF0402JT10R0; ROHS: Yes; Tolerance: 5%
TP11 TP12 = T_POINT_TH: TEST POINT TH PAD 60 DRILL 35 DIAM, NO PART TO ORDER; AGILE_PN: 210-78939; CAD_APPROVED: Yes; HEIGHT: 0.1MM; MFG_NAME01: NA; MFG_PN01: NO PART TO ORDER; ROHS: Yes
U19 = SGTL5000: IC AUDIO CODEC STEREO 8-27MHZ 1.8-3.3V QFN32; AGILE_PN: 315-77907; CAD_APPROVED: Yes; HEIGHT: 0.9MM; MFG_NAME01: FREESCALE SEMICONDUCTOR; MFG_PN01: SGTL5000XNAA3R2; ROHS: Yes
C214-C217 C271 C272 C287 C288 = CAP_NP: CAP CER 10PF 16V 5% C0G 0402; CAD_APPROVED: Yes; FPLIST: CC0402_25,CC0402_HD,0402_CC; HEIGHT: 0.55MM; MFG_NAME01: MURATA; MFG_PN01: GRM1555C1H100JZ01D; ROHS: Yes; Tolerance: 0.25PF
E5 E6 = ANTENNA_2P4GHZ: ANTENNA 2.4GHZ SMT 3.3x1.6x0.65; AGILE_PN: TMP-WF-15702; CAD_APPROVED: Yes; HEIGHT: 0.75MM; MFG_NAME01: ANTENOVA; MFG_PN01: A10381; ROHS: Yes
J20 = MINI_PCI_LATCH_52P: CON 2X26 MINI PCI EXPRESS SMT 0.8MM SP 1136H; AGILE_PN: 211-78711; CAD_APPROVED: Yes; FPLIST: con_2x26_0p8_smt,con_2x26_0p8_smt_a; HEIGHT: 28.85MM; MFG_NAME01: Molex; MFG_PN01: 679100002; ROHS: Yes
R64 = RES: RES MF 22K 1/16W 5% 0402; AGILE_PN: 470-75609; CAD_APPROVED: Yes; FPLIST: RC0402_25,RC0402_HD,0402_CC; MFG_NAME01: SMEC; MFG_PN01: RC73L2Z223JTF; ROHS: Yes; Tolerance: 5%
C225 C226 = CAP_NP: CAP CER 4.7UF 6.3V 10% X5R 0603; CAD_APPROVED: Yes; FPLIST: CC0603_OV,CC0603,0603_CC; HEIGHT: 0.95MM; MFG_NAME01: Murata; MFG_PN01: GRM188R60J475KE19D; ROHS: Yes; Tolerance: 10%
C234-C237 = CAP_POL: CAP TANT  33uF 10V 10% -- 3216-18; AGILE_PN: 150-78749; CAD_APPROVED: Yes; HEIGHT: 1.8MM; MFG_NAME01: AVX; MFG_PN01: TAJA336K010RNJ; ROHS: Yes; Tolerance: 10%
D4 D12 = DIODE_SCHTKY: DIODE SCH PWR RECT 1A 20V SMT; AGILE_PN: 480-75210; CAD_APPROVED: YES; HEIGHT: 1.0MM; MFG_NAME01: ON SEMICONDUCTOR; ROHS: Yes
J22 = USB_A_DUAL: CON 1X4 DUAL USB_TYPE_A_FEMALE RA SHLD TH -- 611H AU 90L; AGILE_PN: 210-75827; CAD_APPROVED: Yes; HEIGHT: 15.51 MM; MFG_NAME01: TYCO ELECTRONICS; MFG_PN01: 5787745-5; ROHS: Yes
L20 = INDUCTOR: IND PWR 10UH@100KHZ 2.3A 20% SMT; AGILE_PN: 180-77610; CAD_APPROVED: Yes; HEIGHT: 2 MM; MFG_NAME01: VISHAY INTERTECHNOLOGY; MFG_PN01: IHLP2020BZER100M01; PART_TYPE: INDUCTOR\POWER; ROHS: Yes; Tolerance: 20%
L21-L26 = INDUCTOR_FERRITE: IND FER BEAD 470 OHM@100MHZ 1A 25% 0603; AGILE_PN: 180-77776; CAD_APPROVED: Yes; FPLIST: IND_0603,IND0603_CC; HEIGHT: 0.95MM; MFG_NAME01: murata; MFG_PN01: BLM18PG471SN1D; PART_TYPE: FERRITE\BEAD; ROHS: Yes; Tolerance: 25%
L31-L33 = 42H171000: IND CHOKE USB2.0 90OHM@100MHz 500mA SMT 0805; AGILE_PN: 180-77702; CAD_APPROVED: Yes; HEIGHT: 1.65MM; MFG_NAME01: COILCRAFT; MFG_PN01: 0805USB-901MLC; PART_TYPE: CHOKE; ROHS: Yes
R132 = RES: RES MF 30.1K  1/16W 1% 0402; AGILE_PN: 470-31000; CAD_APPROVED: Yes; FPLIST: RC0402_25,RC0402_HD,0402_CC; MFG_NAME01: KOA SPEER; MFG_PN01: RK73H1ETTP3012F; ROHS: Yes; Tolerance: 1%
R177 = RES: RES MF 12.0K 1/16W 1% 0402; CAD_APPROVED: Yes; FPLIST: RC0402_25,RC0402_HD,0402_CC; MFG_NAME01: VISHAY; MFG_PN01: CRCW040212K0FKED; ROHS: Yes; Tolerance: 1%
R205 = RES: RES MF 1.0M 1/16W 5% 0402; AGILE_PN: 470-75642; CAD_APPROVED: Yes; FPLIST: RC0402_25,RC0402_HD,0402_CC; MFG_NAME01: VENKEL COMPANY; MFG_PN01: CR0402-16W-105JT; ROHS: Yes; Tolerance: 5%
U20 = LM2735XSD: IC VREG BOOST/SEPIC DC-DC 1.6MHZ 3.0-24V 2.1A 2.7-5.5V LLP6; AGILE_PN: 315-78806; CAD_APPROVED: Yes; HEIGHT: 0.8MM; MFG_NAME01: National Semiconductor; MFG_PN01: LM2735XSD/NOPB; ROHS: Yes
U25 = USB2513_QFN_36P: IC CTLER USB 2.0 HUB 3.3V QFN36; AGILE_PN: 312-79740; CAD_APPROVED: Yes; HEIGHT: 1 MM; MFG_NAME01: SMSC; MFG_PN01: USB2513-AEZG; ROHS: Yes
U31 = ONE_AND: IC GATE AND SGL 2-INP UHS 1.65-5.5V SC70-5; AGILE_PN: 312-30302; CAD_APPROVED: Yes; HEIGHT: 1.1MM; MFG_NAME01: FAIRCHILD; MFG_PN01: NC7SZ08P5_NL; ROHS: Yes
U32 = ST2042_1: IC PWR SW USB SGL 500MA ROHS; CAD_APPROVED: YES; HEIGHT: 1.75 MM; MFG_NAME01: TEXAS INSTRUMENTS; ROHS: Yes
U33 = ST2042_1: IC PWR SW USB DUAL 500MA ROHS; CAD_APPROVED: YES; HEIGHT: 1.75 MM; MFG_NAME01: TEXAS INSTRUMENTS; ROHS: Yes
U35 = 292336-2: CON 1X4 USB_TYPE_A_FEMALE RA SHLD TH 2MM SP 584H AU 142L; AGILE_PN: 210-79629; CAD_APPROVED: Yes; HEIGHT: 14.83MM; MFG_NAME01: TYCO ELECTRONICS; MFG_PN01: 292336-1; ROHS: Yes
U40 = 4X_2IN_OR_14P_HETERO: IC GATE OR QUAD 2-INPUT 2.0 TO 6.0V TSSOP14; AGILE_PN: 312-79665; CAD_APPROVED: Yes; HEIGHT: 1.2MM; MFG_NAME01: ON SEMICONDUCTOR; MFG_PN01: MC74HC32ADTR2G; ROHS: Yes
C242 = CAP_NP: CAP CER 330PF 50V 5% C0G CC0402 ROHS; CAD_APPROVED: Yes; FPLIST: CC0402_25,CC0402_HD,0402_CC; HEIGHT: 0.55MM; MFG_NAME01: MURATA; MFG_PN01: GCM1555C1H331JA16D; ROHS: Yes; Tolerance: 5%
C243 C244 = CAP_NP: CAP CER 18PF 50V 1% C0G 0402; CAD_APPROVED: Yes; FPLIST: CC0402_25,CC0402_HD,0402_CC; HEIGHT: 0.59MM; MFG_NAME01: AVX; MFG_PN01: 04025A180FAT2A; ROHS: Yes; Tolerance: 1%
C273 = CAP_NP: CAP CER 10PF 16V 5% C0G 0402; AGILE_PN: 150-75722; CAD_APPROVED: Yes; FPLIST: CC0402_25,CC0402_HD,0402_CC; HEIGHT: 0.55MM; MFG_NAME01: MURATA; MFG_PN01: GRM1555C1H100JZ01D; ROHS: Yes; Tolerance: 0.25PF
D43 = BAT721B: DIODE SCH DUAL CC 200MA 30V SOT23; AGILE_PN: 480-77944; CAD_APPROVED: Yes; HEIGHT: 1.3MM; MFG_NAME01: Fairchild; ROHS: Yes
D44 = BZX84C27: DIODE ZNR 0.225W 11V SOT23; AGILE_PN: 480-78142; CAD_APPROVED: Yes; HEIGHT: 1.11MM; MFG_NAME01: on semiconductor; ROHS: Yes
J23 = CONN_HDR_4X1: HDR 1X4 TH 100MIL SP 343H SN 110L; AGILE_PN: 210-79977; CAD_APPROVED: Yes; HEIGHT: 8.72MM; MFG_NAME01: 3M; MFG_PN01: 929834-01-04-RK; ROHS: Yes
L27 L28 = INDUCTOR: IND -- 2.2UH@10MHZ 10MA 10% 0402; AGILE_PN: 180-76886; CAD_APPROVED: Yes; FPLIST: IND_0402,0402_CC; HEIGHT: 0.55MM; MFG_NAME01: TDK; MFG_PN01: MLF1005A2R2K; ROHS: Yes; Tolerance: 10%
R179 = RES: RES MF 220K 1/16W 5% 0402; CAD_APPROVED: Yes; FPLIST: RC0402_25,RC0402_HD,0402_CC; MFG_NAME01: Yageo; MFG_PN01: RC0402JR-07220KL; ROHS: Yes; Tolerance: 5%
R204 = RES: RES MF ZERO OHM 1/8W -- 0805; AGILE_PN: 470-75442; CAD_APPROVED: Yes; FPLIST: RC0805_OV,RC0805,0805_CC; MFG_NAME01: BOURNS; MFG_PN01: CR0805-J/-000ELF; ROHS: Yes; Tolerance: 5%
RN8 RN9 = Resistor_Array: RNET ISO 4 ZERO OHM 1/16W 5% CRA04; AGILE_PN: 470-78443; CAD_APPROVED: Yes; FPLIST: CRN_8_0P5_2X1,CRN_8_0P5_2X1_CUST; MFG_NAME01: VISHAY INTERTECHNOLOGY; MFG_PN01: CRA04S0803000Z-RT7-E3; ROHS: Yes; Tolerance: 5%
U17 = PCA9555BS: IC I/O EXPANDER 16-BIT 2.3-5.5V QFN24; AGILE_PN: 312-79833; CAD_APPROVED: Yes; HEIGHT: 1MM; MFG_NAME01: NXP SEMICONDUCTORS; ROHS: Yes
U41 = PICOREAD: IC XCVR NFC 13.56MHz 3.3-5V SSOP16; AGILE_PN: TMP-WF-15569; CAD_APPROVED: Yes; HEIGHT: 1.99MM; MFG_NAME01: INSIDE CONTACTLESS; MFG_PN01: B103B03000000; PRE_APN: 312-80303; ROHS: Yes
Y9 = XTAL_CS10: XTAL 13.56MHZ 18PF SER -- SMT; CAD_APPROVED: Yes; HEIGHT: 1MM; MFG_NAME01: ECS; MFG_PN01: ECS-135.6-18-23A-EN-TR; ROHS: Yes

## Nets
3V3_GATED: C58.1 C147.1 C150.1 C152.1 C154.1 C155.1 C157.1 C183.1 C215.1 C216.1 C271.1 C287.1 C288.1 C294.1 D44.3(CATHODE) J20.2(3.3V_1) J20.3(Reserved1) J20.4(GND7) J20.10(UIM_DATA) J20.12(UIM_CLK) L12.1 R64.1 R77.2 R81.1 R82.1 R128.1 R204.1 U19.20(VDDIO) U41.7(VDDD) ; also on sheet 6 16
3V3_GATED_EN: U17.3(IO0_2) ; also on sheet 16
3V3_ISM: C160.1 C161.1 C162.1 C163.1 C164.1 C165.1 C168.1 C169.1 C170.1 C190.1 J11.6(B3) U4.1(VREFH) U4.19(VDD) U4.35(VBAT2) U4.43(VBAT1(RF)) U4.55(VDD1) U4.56(VDDAD) ; also on sheet 16
3V3_MAIN: C210.1 C211.1 C227.1 C228.1 C229.1 C230.1 R137.1 R138.1 U25.5(VDDA33) U25.10(VDDA33) U25.15(VDD33) U25.23(VDD33) U25.27(VBUS_DET) U25.29(VDD33) U25.36(VDD33) ; also on sheet 7 16
4V2_BACKUP: C196.1 L20.1 R158.1 U20.2(VIN) ; also on sheet 16
5V_LCD_EN: U17.4(IO0_3) ; also on sheet 16
5V_USB: C195.1 C231.1 C232.1 D12.C R132.1 U32.2(IN) U33.2(IN)
5V_USB_REG_EN: R158.2 U20.3(EN) U40.8(Y3)
GND: ANT1.2(GND) C58.2 C61.2 C68.2 C82.2 C145.2 C146.1 C147.2 C150.2 C151.2 C152.2 C154.2 C155.2 C156.2 C157.2 C158.2 C159.2 C160.2 C161.2 C162.2 C163.2 C164.2 C165.2 C166.1 C167.2 C168.2 C169.2 C170.2 C171.2 C172.1 C173.2 C174.2 C175.2 C176.2 C178.2 C179.2 C180.2 C183.2 C184.2 C187.2 C188.2 C189.2 C190.2 C192.2 C194.2 C195.2 C196.2 C197.1 C200.1 C207.2 C209.2 C210.2 C211.2 C212.2 C213.2 C214.2 C215.2 C216.2 C217.2 C225.2 C226.2 C227.2 C228.2 C229.2 C230.2 C231.2 C232.2 C234.2 C235.2 C236.2 C237.2 C238.2 C239.2 C240.2 C241.2 C243.2 C244.2 C267.2 C268.2 C269.2 C270.2 C271.2 C272.2 C273.2 C274.2 C287.2 C288.2 C294.2 C297.2 C298.2 C300.2 D43.3 D44.1(ANODE) E5.1 E6.1 J9.2(GND1) J9.3(GND2) J10.2(GND1) J10.3(GND2) J11.2(B1) J12.2(GND1) J12.3(GND2) J14.2(GND1) J14.3(GND2) J16.2 J20.6(1.5V_1) J20.8(UIM_PWR) J20.9(GND1) J20.13(REFCLK+) J20.14(UIM_RESET) J20.24(+3.3Vaux) J20.26(GND9) J20.48(1.5V_3) J20.50(GND12) J20.52(3.3V_2) J23.2 L13.2 L23.1 L25.1 L26.1 L30.2 Q4.2(SOURCE) R75.2 R76.2 R78.1 R80.2 R96.2 R129.2 R130.2 R131.2 R136.2 R141.2 R142.2 R147.2 R166.1 R167.1 R168.2 R169.1 R169.2 R170.2 R171.1 R171.2 R177.2 U4.2(VREFL) U4.3(VSSAD) U4.4(VSS1) U4.20(VSS2) U4.36(GND) U4.38(GND_PA2(RF)) U4.40(GND_PA1(RF)) U4.61(VSS3) U4.62(VSS4) U15.58(RF_GND) U15.75(VSS_1) U15.76(VSS_2) U15.77(VSS_3) U15.78(VSS_4) U15.79(VSS_5) U15.84(VSS_6) U15.85(VSS_7) U15.86(VSS_8) U15.87(VSS_9) U15.88(VSS_10) U15.93(VSS_11) U15.94(VSS_12) U15.95(VSS_13) U15.96(VSS_14) U15.97(VSS_15) U15.104(VSS_16) U15.105(VSS_17) U15.106(VSS_18) U15.115(VSS_19) U17.9(VSS) U17.23(A1) U17.25(EP) U19.1(GND1) U19.3(GND2) U19.7(AGND) U19.33(GND3-PAD) U20.1(PGND) U20.5(AGND) U20.7(EP) U25.37(VSS_EPAD) U31.3(DGND) U32.1(GND) U32.9(PAD) U33.1(GND) U33.9(PAD) U40.7(GND) U41.5(~{NRD}) U41.6(~{NWR}) U41.10(GND) U41.16(GNDA) Y4.2 Y4.4 Y5.2(GND) Y5.4(GND) Y7.2(GND) Y7.4(GND) ; also on sheet 5 6 7 8 9 16 17
VBUS_BOT: C235.1 C239.1 L22.1 U32.6(OUT2)
VBUS_MODEM: C237.1 C238.1 L24.1 U33.6(OUT2)
VBUS_OTG: C236.1 C241.1 D4.C ; also on sheet 7 17
VBUS_TOP: C234.1 C240.1 L21.1 U32.7(OUT1)
BKGD: J11.1(A1) U4.34(PTA4/ACMP1O/BKGD/MS)
BT_ACTIVE: J20.41(Reserved5) ; also on sheet 7
BT_HOST_WAKE: J20.43(Reserved6) U17.13(IO1_3)
BT_RESET_B: J20.42(LED_WWAN#) U17.16(IO1_6)
DCDC_VDDIO_3V3: C187.1 C217.1 C272.1 J20.1(WAKE#) J20.32(SMB_DATA) R66.2 R109.1 R134.2 U17.18(A0) U17.21(VDD) U17.24(A2) U31.5(3V3) U40.14(VCC) ; also on sheet 6 7 8 9 16 17
DIG_REG: U15.124(DIG_REG)
DUAL_GND: C302.2 C303.2 J22.A4(GND) J22.B4(GND_B) J22.S1(SGND1) J22.S2(SGND2) J22.S3(SGND3) J22.S4(SGND4) L23.2 L25.2
EN_BOT: U25.18(PRTPWR3) U32.4(EN2) U40.4(A2)
EN_MODEM: R108.2 U31.4(OUT) U33.4(EN2) U40.12(A4)
EN_TOP: U25.16(PRTPWR2) U32.3(EN1) U40.5(B2)
ENET_INT: U17.11(IO1_1) ; also on sheet 6
ENET_RESET_B: U17.7(IO0_6) ; also on sheet 6
HP_GND: J15.2 J18.1 L13.1 U19.4(HP_VGND)
HP_L: C213.1 C267.1 J15.1 J18.3 U19.6(HP_L)
HP_R: C212.1 C268.1 J15.3 J18.2 U19.2(HP_R)
I2C_SCL: R95.2 U4.24(PTA3/KBI1P3/SCL/ADP3) U17.19(SCL) U19.29(CTRL_CLK) ; also on sheet 6
I2C_SDA: R94.2 U4.25(PTA2/KBI1P2/SDA/ADP2) U17.20(SDA) U19.27(CTRL_DATA) ; also on sheet 6
IO_EXP_INT_B: R109.2 U17.22(\~{INT}) ; also on sheet 8
ISM_DIO5: TP8.1(Pin1) U4.5(EXTAL/SCL/PTB7) U4.54(DIO5/CLKOUT)
ISM_DIR: U4.32(PTC4/TPM3CH4) U4.37(RXTX(RF))
ISM_GPIO: U4.14(PTB2/KBI1P6/ADP6) U17.14(IO1_4)
ISM_LED: U4.8(PTB4/TPM2CH1) ; also on sheet 7
ISM_RESET_B: J11.4(B2) R66.1 U4.33(PTA5/IRQ/TPM1CLK/~{RESET}) U17.8(IO0_7)
ISM_RF_RESET: U4.12(PTC0/TPM3CH0) U4.48(~{RESET})
ISM_RFIO: L7.1 U4.39(RFIO(RF))
ISM_UART_RX: TP14.1(Pin1) U4.15(PTB1/KBI1P5/TXD1/ADP5)
ISM_UART_TX: TP13.1(Pin1) U4.16(PTB0/KBI1P4/RXD1/ADP4)
ISM_XTA: C171.1 U4.46(XTA) Y4.1
ISM_XTB: C172.2 U4.47(XTB) Y4.3
JTAG_RTCK: R125.2 ; also on sheet 17
JTAG_TCK: U15.11(TCK/GPIO47) ; also on sheet 17
JTAG_TMS: U15.12(TMS/GPIO46) ; also on sheet 17
JTAG_TRST_B: R146.1 ; also on sheet 17
JTAG_ZB_TDI: U15.10(TDI/GPIO48) ; also on sheet 17
JTAG_ZB_TDO: U15.9(TDO/GPIO49) ; also on sheet 17
LCD_CARD_PRESENT: U17.17(IO1_7) ; also on sheet 7
MIC: C159.1 C270.1 C299.2 U19.15(MIC)
MIC_BIAS: C158.1 C269.1 C300.1 J16.3 R209.1 U19.16(MIC_BIAS)
MODEM_GND: C301.2 L26.2 U35.4(GND_B) U35.S1 U35.S2 U35.S3 U35.S4
MODEM_VBUS_EN: U31.1(IN_B) ; also on sheet 6
NVM_REG: U15.133(NVM_REG)
OC_BOT: U25.19(OCS3_N) U32.5(~{OC2})
OC_MODEM: U25.13(OCS1_N) U33.5(~{OC2})
OC_TOP: U25.17(OCS2_N) U32.8(~{OC1})
PICOREAD_ANT1: D43.2 L27.1 U41.8(ANT1)
PICOREAD_ANT2: D43.1 L28.1 U41.9(ANT2)
PICOREAD_REC: R179.1 U41.15(REC)
PICOREAD_SPI_MISO: RN8.7(PIN7) RN9.6(PIN6) U41.2(DOUT/AD1)
PICOREAD_SPI_MOSI: RN8.5(PIN5) RN9.8(PIN8) U41.3(DIN/AD0)
PICOREAD_SPI_SCK: RN8.8(PIN8) RN9.5(PIN5) U41.4(SCK/IRQ)
PICOREAD_SPI_SS: RN8.6(PIN6) RN9.7(PIN7) U41.1(~{CS})
PICOREAD_VDDA: C175.1 C273.1 C274.1 R204.2 U41.14(VDDA)
PICOREAD_XTAL1: C243.1 U41.12(XTAL1) Y9.1
PICOREAD_XTAL2: C244.1 U41.11(XTAL2) Y9.2
RF_BIAS: U15.55(RF_BIAS)
RF_PLL_FLT: U15.46(RF_PLL_FLT)
SAIF0_BITCLK: R202.1 ; also on sheet 6
SAIF0_DIN: R199.1 ; also on sheet 6
SAIF0_DOUT: R200.1 ; also on sheet 6
SAIF0_LRCLK: R201.1 ; also on sheet 6
SAIF0_MCLK: R203.1 ; also on sheet 6
SPI2_MISO: RN9.3(PIN3) ; also on sheet 8
SPI2_MOSI: RN9.1(PIN1) ; also on sheet 8
SPI2_SCK: RN9.4(PIN4) ; also on sheet 8
SPI2_SS: RN9.2(PIN2) ; also on sheet 8
UART0_CTS: J20.44(LED_WLAN#) ; also on sheet 6
UART0_RTS: J20.45(Reserved7) ; also on sheet 6
UART0_RX: J20.46(LED_WPAN#) ; also on sheet 6
UART0_TX: J20.47(Reserved8) ; also on sheet 6
UART1_RX: R157.2 ; also on sheet 6
UART1_TX: R156.2 ; also on sheet 6
USB1_DM: U25.30(USBUP_DM) ; also on sheet 17
USB1_DP: U25.31(USBUP_DP) ; also on sheet 17
USB_BOT_DM: L32.1 U25.6(USBDN3_DM/PRT_DIS_M3)
USB_BOT_DP: L32.4 U25.7(USBDN3_DP/PRT_DIS_P3)
USB_HUB_RST_B: U17.15(IO1_5) U25.26(RESET_N)
USB_MODEM_DM: L33.4 U25.1(USBDN1_DM/PRT_DIS_M1)
USB_MODEM_DP: L33.1 U25.2(USBDN1_DP/PRT_DIS_P1)
USB_TOP_DM: L31.1 U25.3(USBDN2_DM/PRT_DIS_M2)
USB_TOP_DP: L31.4 U25.4(USBDN2_DP/PRT_DIS_P2)
USBOTG_OC: U33.8(~{OC1}) ; also on sheet 8
USBOTG_VBUS_EN: U17.1(IO0_0) U33.3(EN1) U40.13(B4)
VR_ANA: C166.2 C188.1 U4.44(VR_ANA)
VR_DIG: C167.1 C189.1 U4.45(VR_DIG)
VR_PA: C173.1 C174.1 C176.1 L6.1 U4.42(VR_PA)
WIFI_SDIO_CLK: J20.25(PERp0) ; also on sheet 8
WIFI_SDIO_CMD: J20.29(GND5) R64.2 ; also on sheet 8
WIFI_SDIO_D0: J20.23(PERn0) ; also on sheet 8
WIFI_SDIO_D1: J20.27(GND4) ; also on sheet 8
WIFI_SDIO_D2: J20.28(1.5V_2) ; also on sheet 8
WIFI_SDIO_D3: J20.30(SMB_CLK) ; also on sheet 8
WL_RF_1V8: C151.1 C214.1 J20.11(REFCLK-) ; also on sheet 16
WLAN_ACTIVE: J20.49(Reserved9) ; also on sheet 7
WLAN_PDN: J20.22(PERST#) U17.6(IO0_5)
WLAN_WAKE: J20.21(GND3) U17.12(IO1_2)
ZB_SPI_MISO: RN8.2(PIN2) U15.29(SPI_MISO/GPIO5) U15.34(SSI_TX/GPIO0)
ZB_SPI_MOSI: RN8.4(PIN4) U15.28(SPI_MOSI/GPIO6)
ZB_SPI_SCK: RN8.1(PIN1) U15.27(SPI_SCK/GPIO7)
ZB_SPI_SS: RN8.3(PIN3) U15.30(SPI_SS/GPIO4)
ZIGBEE_FLASH_ERASE: R145.1 U17.2(IO0_1)
ZIGBEE_GPIO: U15.33(SSI_RX/GPIO1) ; also on sheet 6
ZIGBEE_LED: U15.26(TMR0/GPIO8) ; also on sheet 7
ZIGBEE_RESET_B: R80.1 R146.2 U15.51(~{RESET}) U17.5(IO0_4)
N20112384: C156.1 C184.1 L10.2 R82.2 U15.44(LREG_BK_FB)
N20121042: D6.A L10.1 U15.43(COIL_BK)
N20123696: D6.C R81.2 U15.45(VBATT)
N20135512: Q4.1(GATE) R75.1 R76.1 R145.2 U15.61(ADC2_VREFL/GPIO39)
N20137474: Q4.3(DRAIN) R77.1 U15.64(ADC2_VREFH/GPIO38)
N20150953: C182.2 J12.1(CTR)
N20151194: C181.1 C182.1 U15.60(RF_RX_TX)
N20157126: U15.50(XTAL_24_IN) Y5.1
N20157653: U15.49(XTAL_24_OUT) Y5.3
N20614471: C177.1 C178.1 L6.2 L7.2
N20623476: C177.2 C194.1 L8.1
N20623914: C179.1 L8.2 L9.1
N20639994: C180.1 C191.2 C193.1 L9.2
N22010545: R157.1 U15.20(UART1_TX/GPIO14)
N24612024: ANT1.1(Signal) C181.2
N25368576: R78.2 U15.17(UART1_RTS/GPIO17)
N25879518: C193.2 J10.1(CTR) L30.1
N25882006: C191.1 C192.1
N25942077: R125.1 U15.8(ADC7/RTCK/GPIO37)
N26302633: R199.2 U19.25(I2S_DOUT)
N26303165: R200.2 U19.26(I2S_DIN)
N26303698: R201.2 U19.23(I2S_LRCLK)
N26304232: R202.2 U19.24(I2S_SCLK)
N26306493: R203.2 U19.21(SYS_MCLK)
N26311614: C61.1 L12.2 U19.5(VDDA)
N26315679: R128.2 U19.30(VDDD)
N26322683: C68.1 U19.18(CPFILT)
N26324953: C82.1 U19.10(VAG)
N26335790: TP12.1(TP) U19.12(LINEOUT_L)
N26335836: TP11.1(TP) U19.11(LINEOUT_R)
N26352753: R129.1 R134.1 U19.31(CTRL_ADR0_CS)
N26353356: R130.1 U19.32(CTRL_MODE)
N27773305: D12.A L20.2 U20.6(SW)
N27773317: R131.1 R132.2 U20.4(FB)
N28722713: C303.1 J22.A1(VCC) L21.2
N28726188: C146.2 R205.1 U25.32(XTALOUT) Y7.1
N28726198: C145.1 R205.2 U25.33(XTALIN/CLKIN) Y7.3
N28726415: R177.1 U25.35(RBIAS)
N28726934: C225.1 U25.14(CRFILT)
N28727026: C226.1 U25.34(PLLFILT)
N28727439: R136.1 R137.2 U25.25(HS_IND/CFG_SEL1)
N28728688: R138.2 R147.1 U25.28(SUSP_IND/LOCAL_PWR/NON_REM0)
N28737757: D4.A U33.7(OUT1)
N28783725: R95.1 R141.1 U25.24(SCL/SMBCLK/CFG_SEL0)
N28784781: R94.1 R142.1 U25.22(SDA/SMBDATA/NON_REM1)
N28787165: C301.1 L24.2 U35.1(VCC_B)
N28847997: U40.10(B3) U40.11(Y4)
N28848006: U40.6(Y2) U40.9(A3)
N28853722: R108.1 U25.12(PRTPWR1) U31.2(IN_A)
N28886082: C302.1 J22.B1(VCC_B) L22.2
N28976429: C242.2 J23.4 R97.2
N28976672: C197.2 C200.2 J23.3 L27.2 R97.1 R99.2
N28977107: C207.1 C209.1 J23.1 L28.2 R99.1
N28977635: C242.1 R179.2
N29039241: L33.3 U35.2(DATA-)
N29039246: L33.2 U35.3(DATA+)
N29040204: J22.A2(DATA+) L31.2
N29040213: J22.A3(DATA-) L31.3
N29040310: J22.B2(DATA+_B) L32.2
N29040319: J22.B3(data-_B) L32.3
N29125794: R96.1 U41.13(TEST)
N29157230: R156.1 U15.19(UART1_RX/GPIO15)
N29175701: J9.1(CTR) R166.2 R168.1
N29175849: J14.1(CTR) R167.2 R170.1
N29213138: C297.1 E5.2
N29213145: C298.1 E6.2
N29243151: C299.1 J16.1 R209.2

Not connected (* = marked no-connect by the designer): D44 2(NC)*; J11 3(A2)* 5(A3)*; J20 5(Reserved2)* 7(CLKREQ#)* 15(GND2)* 16(UIM_VPP)* 17(Reserved/UIM_C8)* 18(GND8)* 19(Reserved/UIM_C4)* 20(W_DISABLE#)* 31(PETn0)* 33(PETp0)* 34(GND10)* 35(GND6)* 36(USB_D-)* 37(Reserved3)* 38(USB_D+)* 39(Reserved4)* 40(GND11)* 51(Reserved10)*; U4 6(XTAL/SDA/PTB6)* 7(PTB5/TPM1CH1)* 9(PTC3/TPM3CH3)* 10(PTC2/TPM3CH2) 11(PTC1/TPM3CH1) 13(PTB3/KBI1P7/ADP7)* 17(PTA7/TPM2CH2/ADP9)* 18(PTA6/TPM1CH2/ADP8)* 21(PTD4/KBI2P4)* 22(PTD3/KBI2P3)* 23(PTD2/KBI2P2)* 26(PTA1/KBI1P1/TPM2CH0/ADP1/ACMP-) 27(PTA0/KBI1P0/TPM1CH0/ADP0/ACMP+) 28(PTC7/TXD2/ACMP2-) 29(PTC6/RXD2/ACMP2+) 30(NC)* 31(PTC5/TPM3CH5/ACMP2O)* 41(PA_BOOST)* 49(DIO0/PTD1/KBI2P1)* 50(DIO1/PTD0/KBI2P0)* 51(DIO2)* 52(DIO3)* 53(DIO4)* 57(SPSCK) 58(MOSI) 59(~{SS}) 60(MISO); U15 1(ADC0/GPIO30)* 2(ADC1/GPIO31)* 3(ADC2/GPIO32)* 4(ADC3/GPIO33)* 5(ADC4/GPIO34)* 6(ADC5/GPIO35)* 7(ADC6/GPIO36)* 13(UART2_RTS/GPIO21)* 14(UART2_CTS/GPIO20)* 15(UART2_RX/GPIO19)* 16(UART2_TX/GPIO18)* 18(UART1_CTS/GPIO16)* 21(I2C_SDA/GPIO13)* 22(I2C_SCL/GPIO12)* 23(TMR3/GPIO11)* 24(TMR2/GPIO10)* 25(TMR1/GPIO9)* 31(SSI_BITCK/GPIO3)* 32(SSI_FSYN/GPIO2)* 35(KBI_7/GPIO29)* 36(KBI_6/GPIO28)* 37(KBI_5/GPIO27)* 38(KBI_4/GPIO26)* 39(KBI_3/GPIO25)* 40(KBI_2/GPIO24)* 41(KBI_1/GPIO23)* 42(KBI_0/HST_WK/GPIO22)* 47(XTAL_32_IN)* 48(XTAL_32_OUT)* 52(TX_ON/GPIO44)* 53(PA_NEG)* 54(PA_POS)* 56(ANT_1/GPIO42)* 57(ANT_2/GPIO43)* 59(RX_ON/GPIO45)* 62(ADC1_VREFL/GPIO41)* 63(ADC1_VREFH/GPIO40)* 65(NC)* 66(NC)* 67(NC)* 68(NC)* 69(NC)* 70(NC)* 71(NC)* 72(NC)* 73(NC)* 74(NC)* 80(NC)* 81(NC)* 82(NC)* 83(NC)* 89(NC)* 90(NC)* 91(NC)* 92(NC)* 98(NC)* 99(NC)* 100(NC)* 101(NC)* 102(MDO01/GPIO52)* 103(MDO00/GPIO51)* 107(NC)* 108(NC)* 109(NC)* 110(NC)* 111(MDO03/GPIO54)* 112(MDO02/GPIO53)* 113(~{MSEO1}/GPIO60)* 114(~{MSEO0}/GPIO59)* 116(NC)* 117(NC)* 118(NC)* 119(NC)* 120(MDO05/GPIO56)* 121(MDO04/GPIO55)* 122(~{RDY}/GPIO61)* 123(~{EVTO}/GPIO62)* 125(NC)* 126(NC)* 127(NC)* 128(NC)* 129(MDO07/GPIO58)* 130(MDO06/GPIO57)* 131(MCKO/GPIO50)* 132(~{EVTI}/GPIO63)* 134(NC)* 135(NC)* 136(NC)* 137(NC)* 138(NC)* 139(NC)* 140(NC)* 141(NC)* 142(NC)* 143(NC)* 144(NC)* 145(NC)*; U17 10(IO1_0)*; U19 8(NC1)* 9(NC2)* 13(LINEIN_R)* 14(LINEIN_L)* 17(NC3)* 19(NC4)* 22(NC5)* 28(NC6)*; U25 8(NC8)* 9(NC9)* 11(TEST)* 20(NC20)* 21(NC21)*; U40 1(A1)* 2(B1)* 3(Y1)*

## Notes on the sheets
sheet 10
- Built-in
  regulators
- PA_BOOST should be
  used for  transmit
  if more than 13dBm
  is needed (up to
  17dBm)
- Adjust load capacitance value
  to the crystal that will be
  ordered (8-22pf range)
- GPIO for MCU power
  down / CPU wake
- PCB antenna trace
- RFIO used for receive
  and transmit up to
  13dBm
sheet 11
- 50 Ohm line
- PLACE FAR FROM
  WIFI SECTION
- 50 Ohm line
- 50 Ohm line
- U.FL Antenna
  connector
- RTS = input
- CTS = output
- Have RESETB active by
  default, activation
  by CPU only
- 32.768kHz is
  optional
sheet 12
- I2C address for SGTL5000
  CTRL_ADR0_CS = 0 => I2C address 0x0A
  CTRL_ADR0_CS = 1 => I2C address 0x2A
sheet 13
- MiniPCIe  card has u.FL
  connectors. place antennas on the
  PCB to connect with u.FL - u.FL
  cable and avoid having floating
  antennas.
- Wifi Antenna
- BT Antenna
sheet 14
- ACTIVE HIGH
- ACTIVE HIGH
- 100ppm
- ACTIVE HIGH
sheet 15
- NRD/NWR to
  GND =
  selects SPI
  interface
- SPI2 signals
- I2C address : 0x25
